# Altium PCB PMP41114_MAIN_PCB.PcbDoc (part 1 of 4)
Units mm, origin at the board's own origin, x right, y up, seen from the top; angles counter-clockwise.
Board outline 159.1 x 70 mm, 6 copper layers (Top Layer, Signal Layer 1, Signal Layer 2, Signal Layer 3, Signal Layer 4, Bottom Layer), stack 1.671 mm thick; 188 components, 146 nets, 720 pads, 326 vias.
Unrouted connection lines stored in the file: 209.
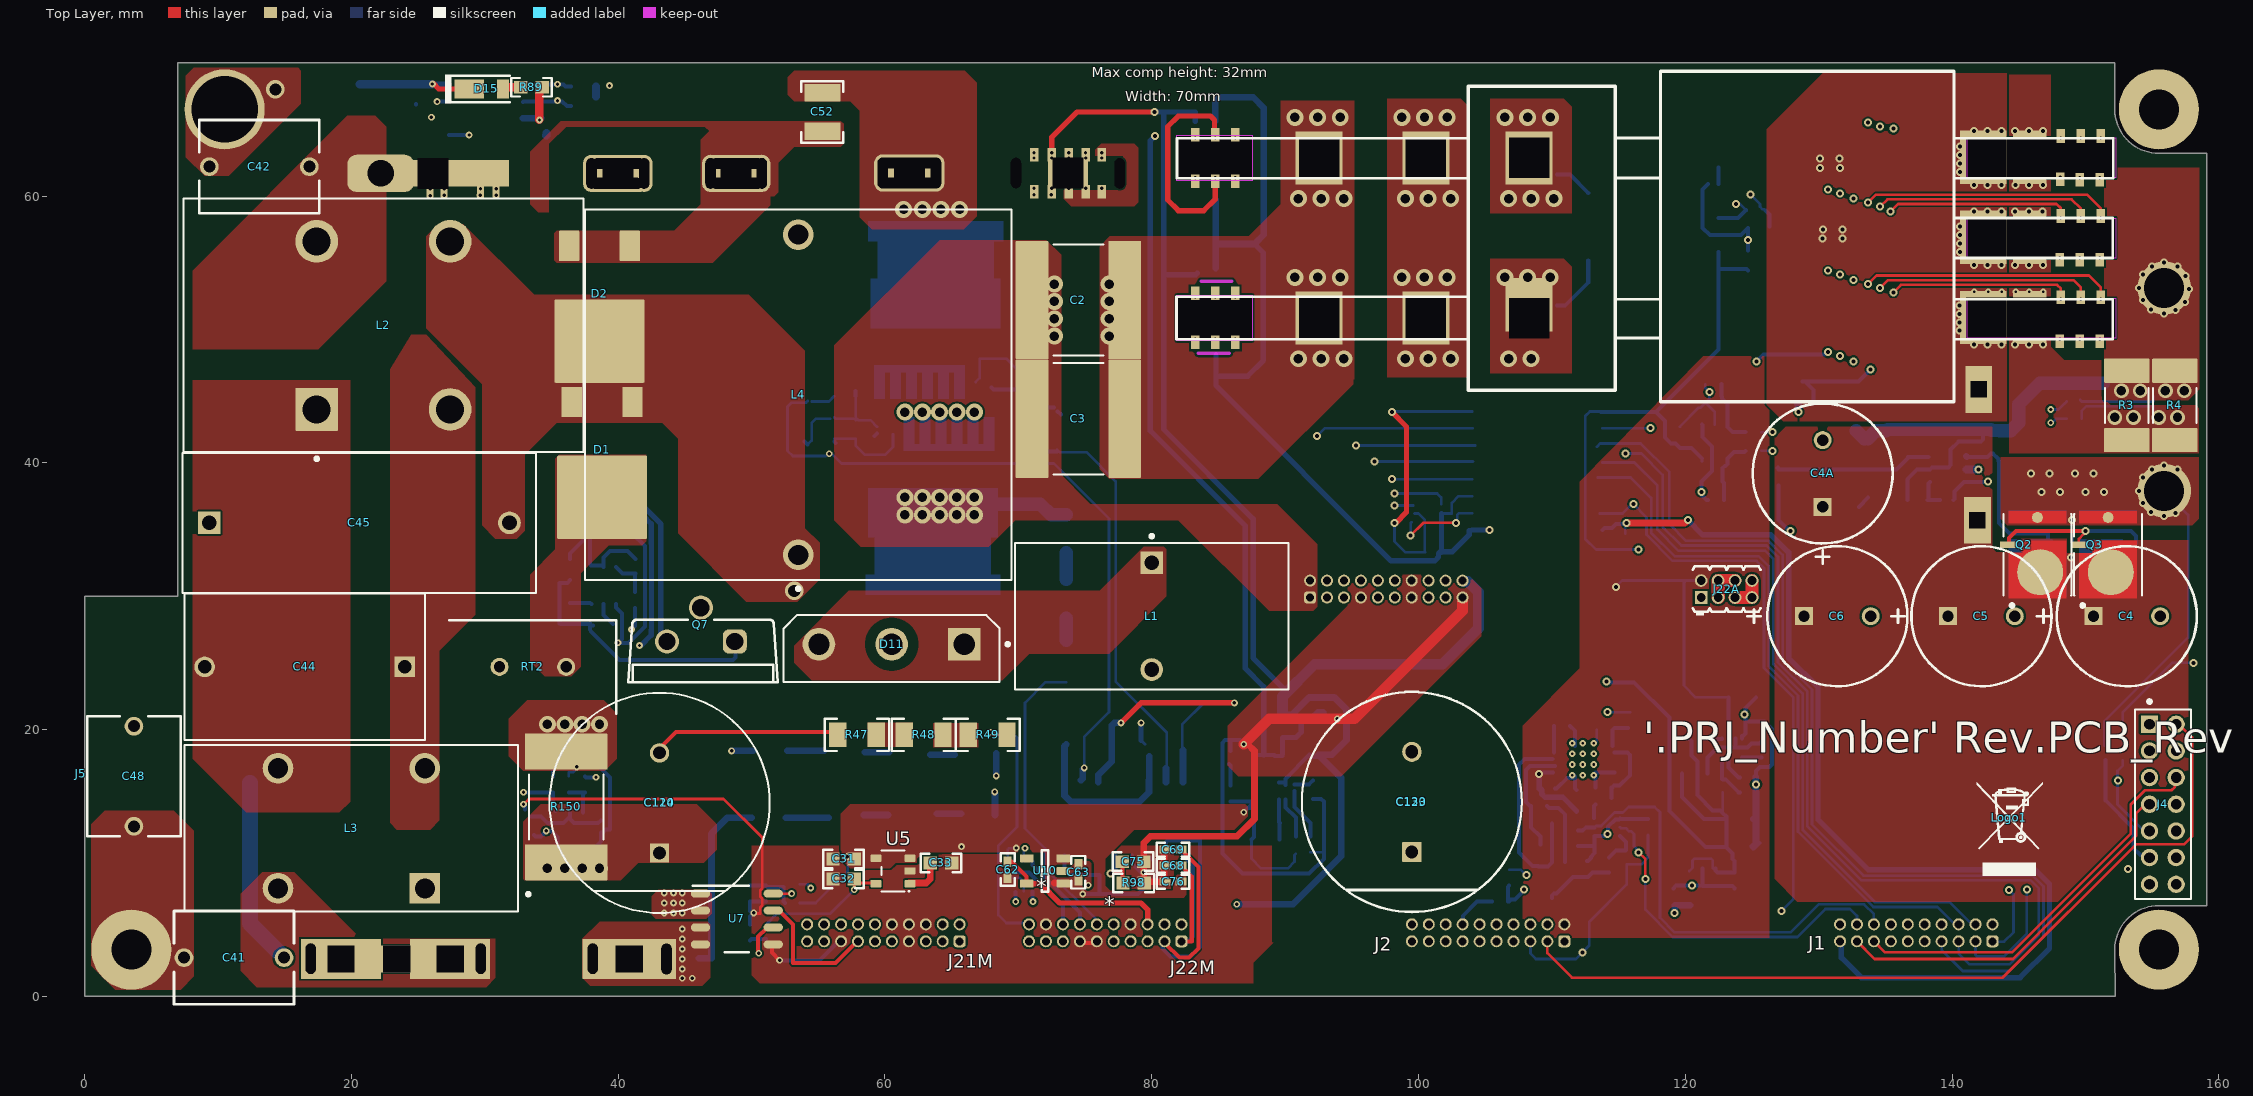
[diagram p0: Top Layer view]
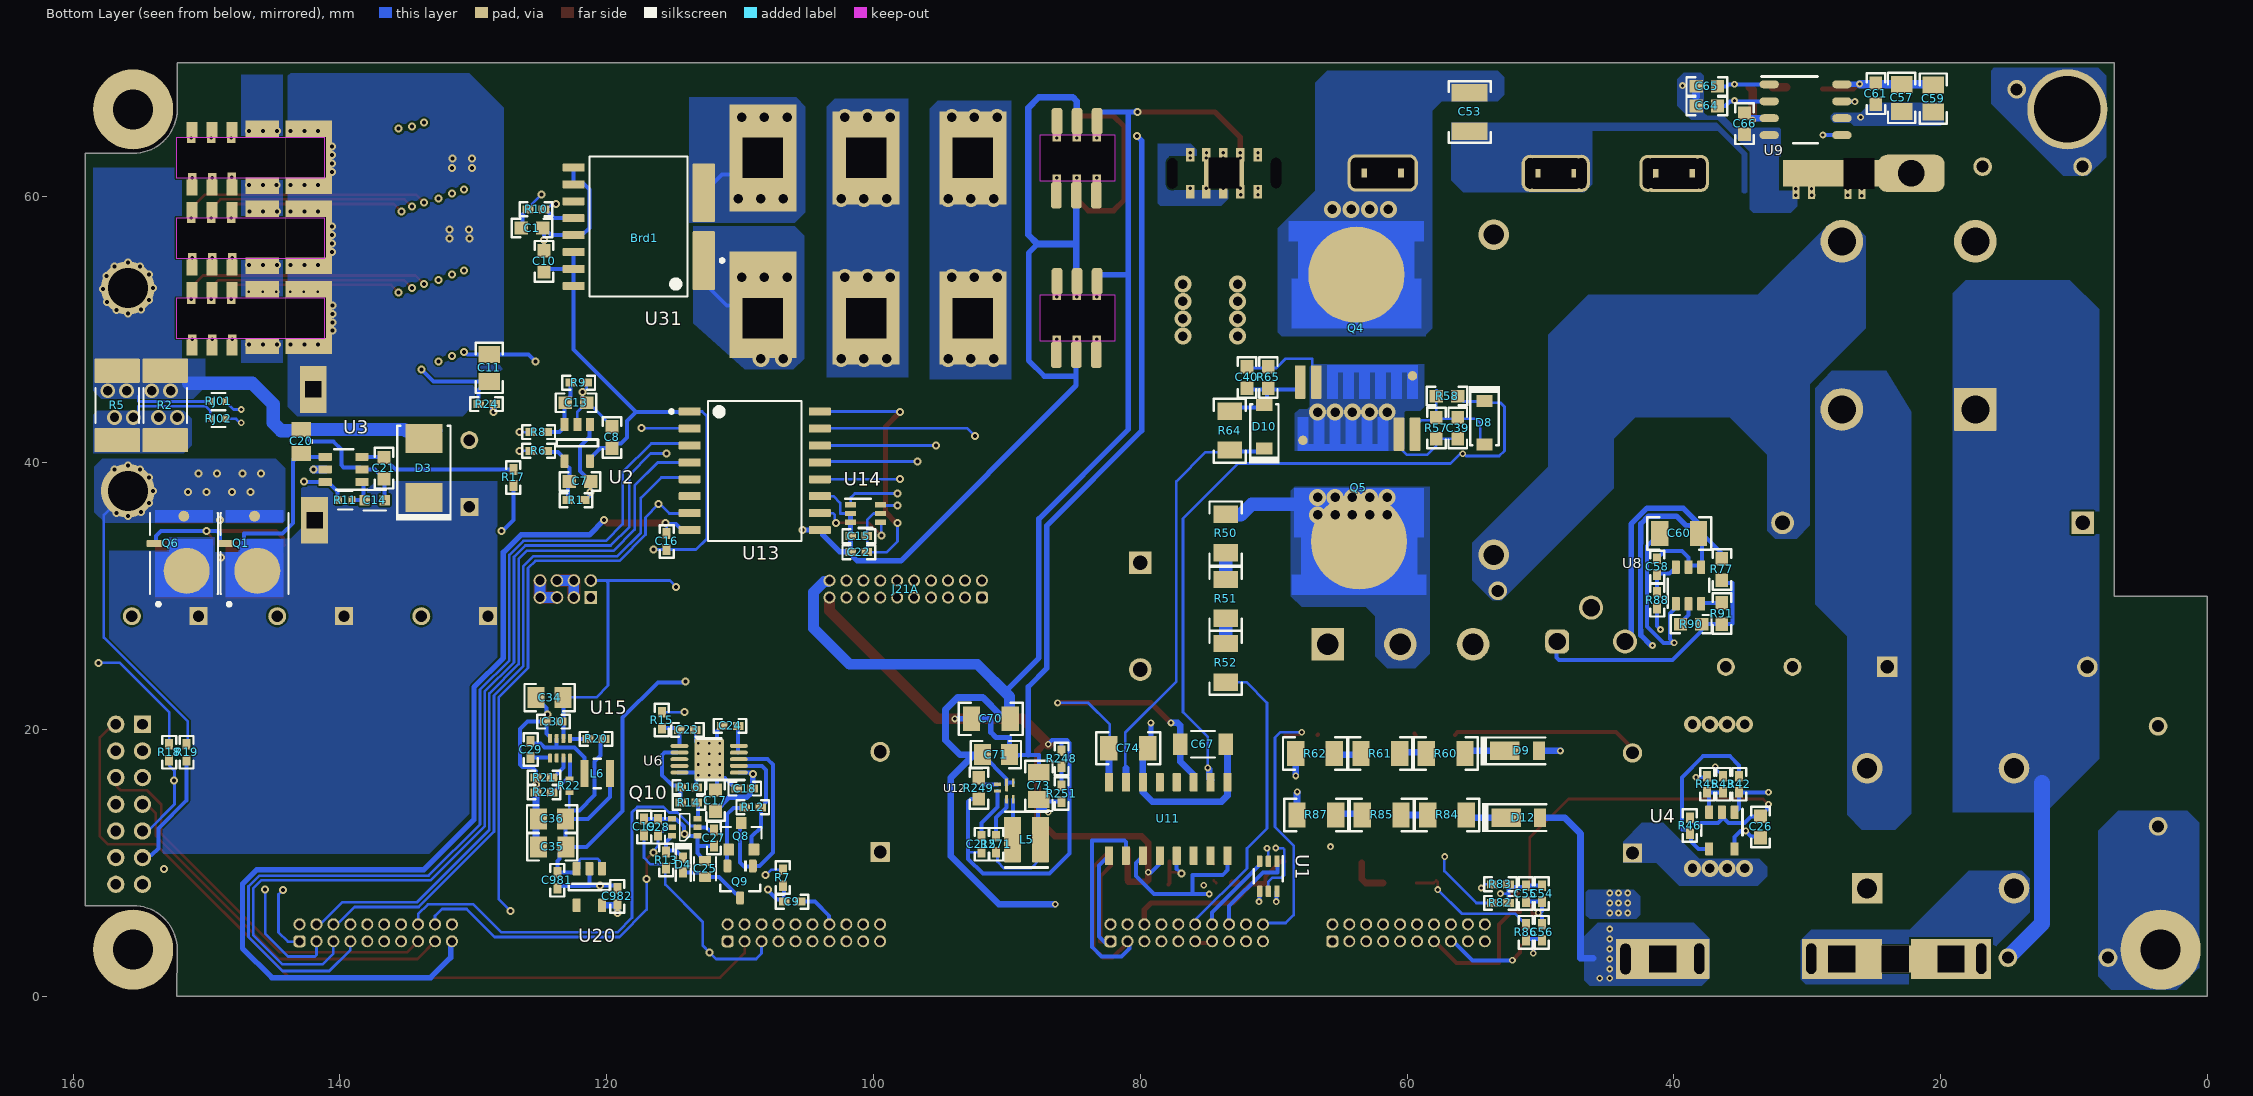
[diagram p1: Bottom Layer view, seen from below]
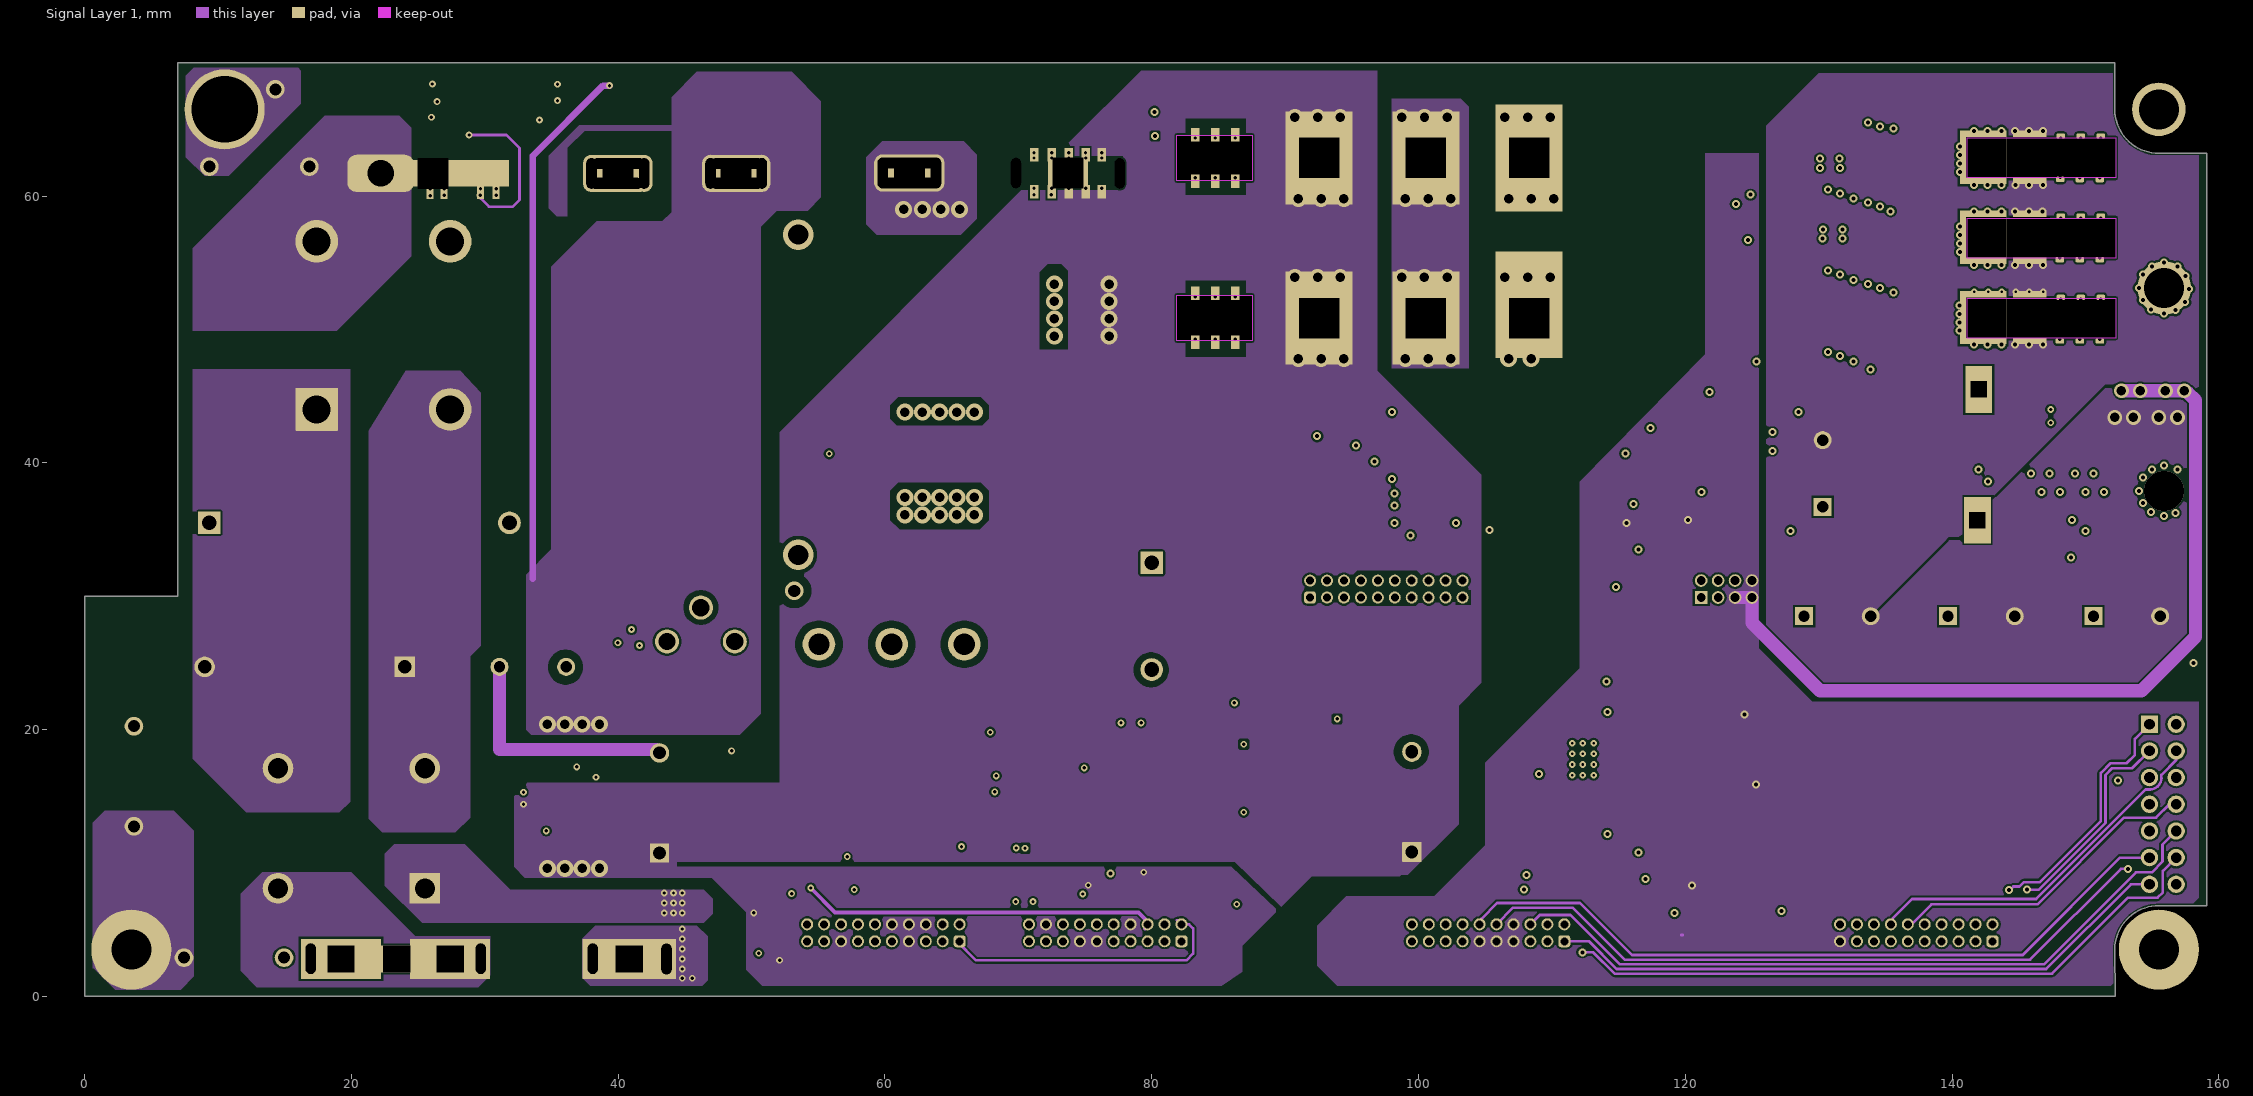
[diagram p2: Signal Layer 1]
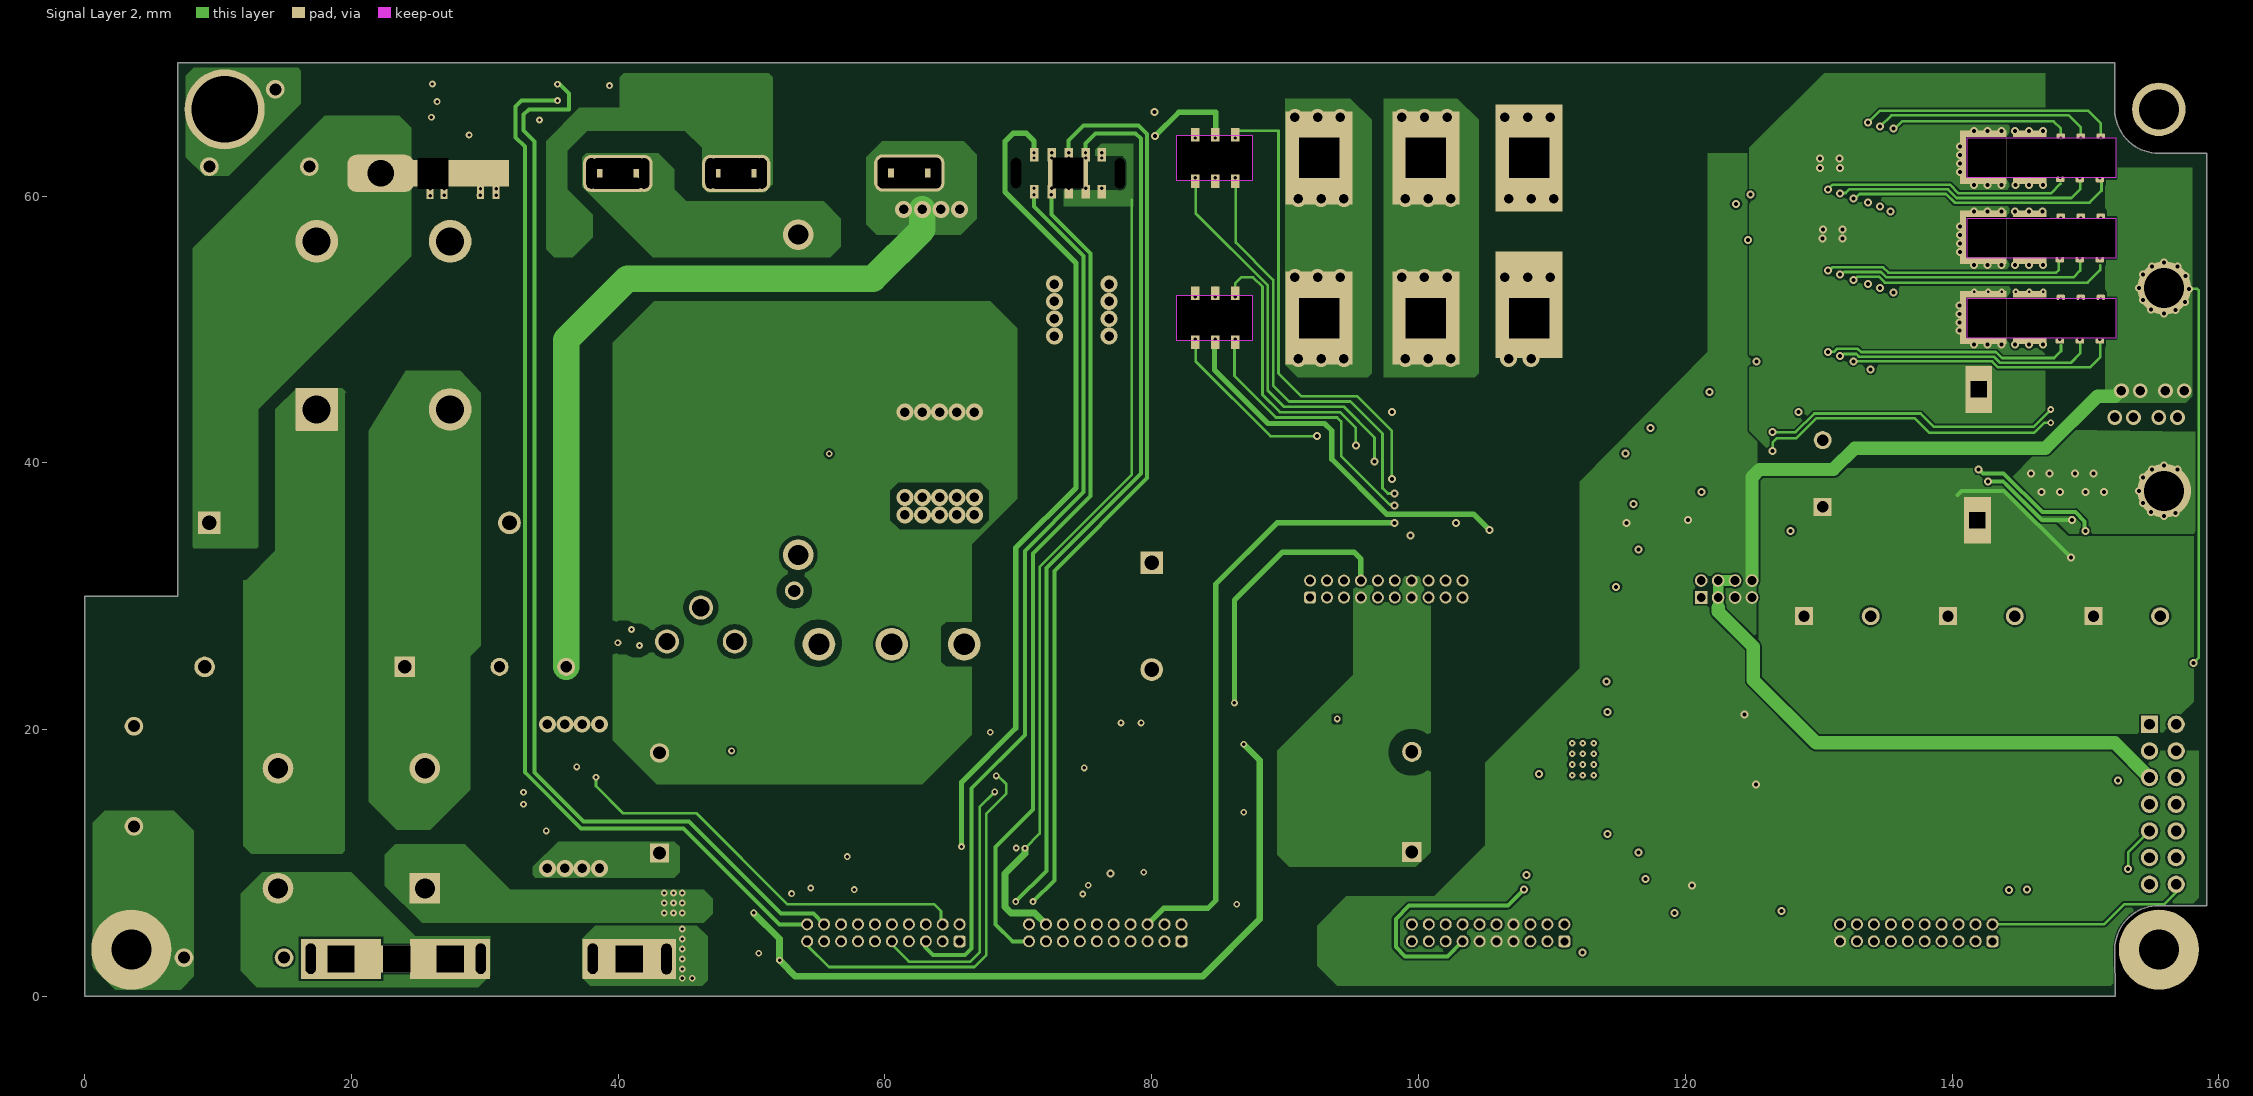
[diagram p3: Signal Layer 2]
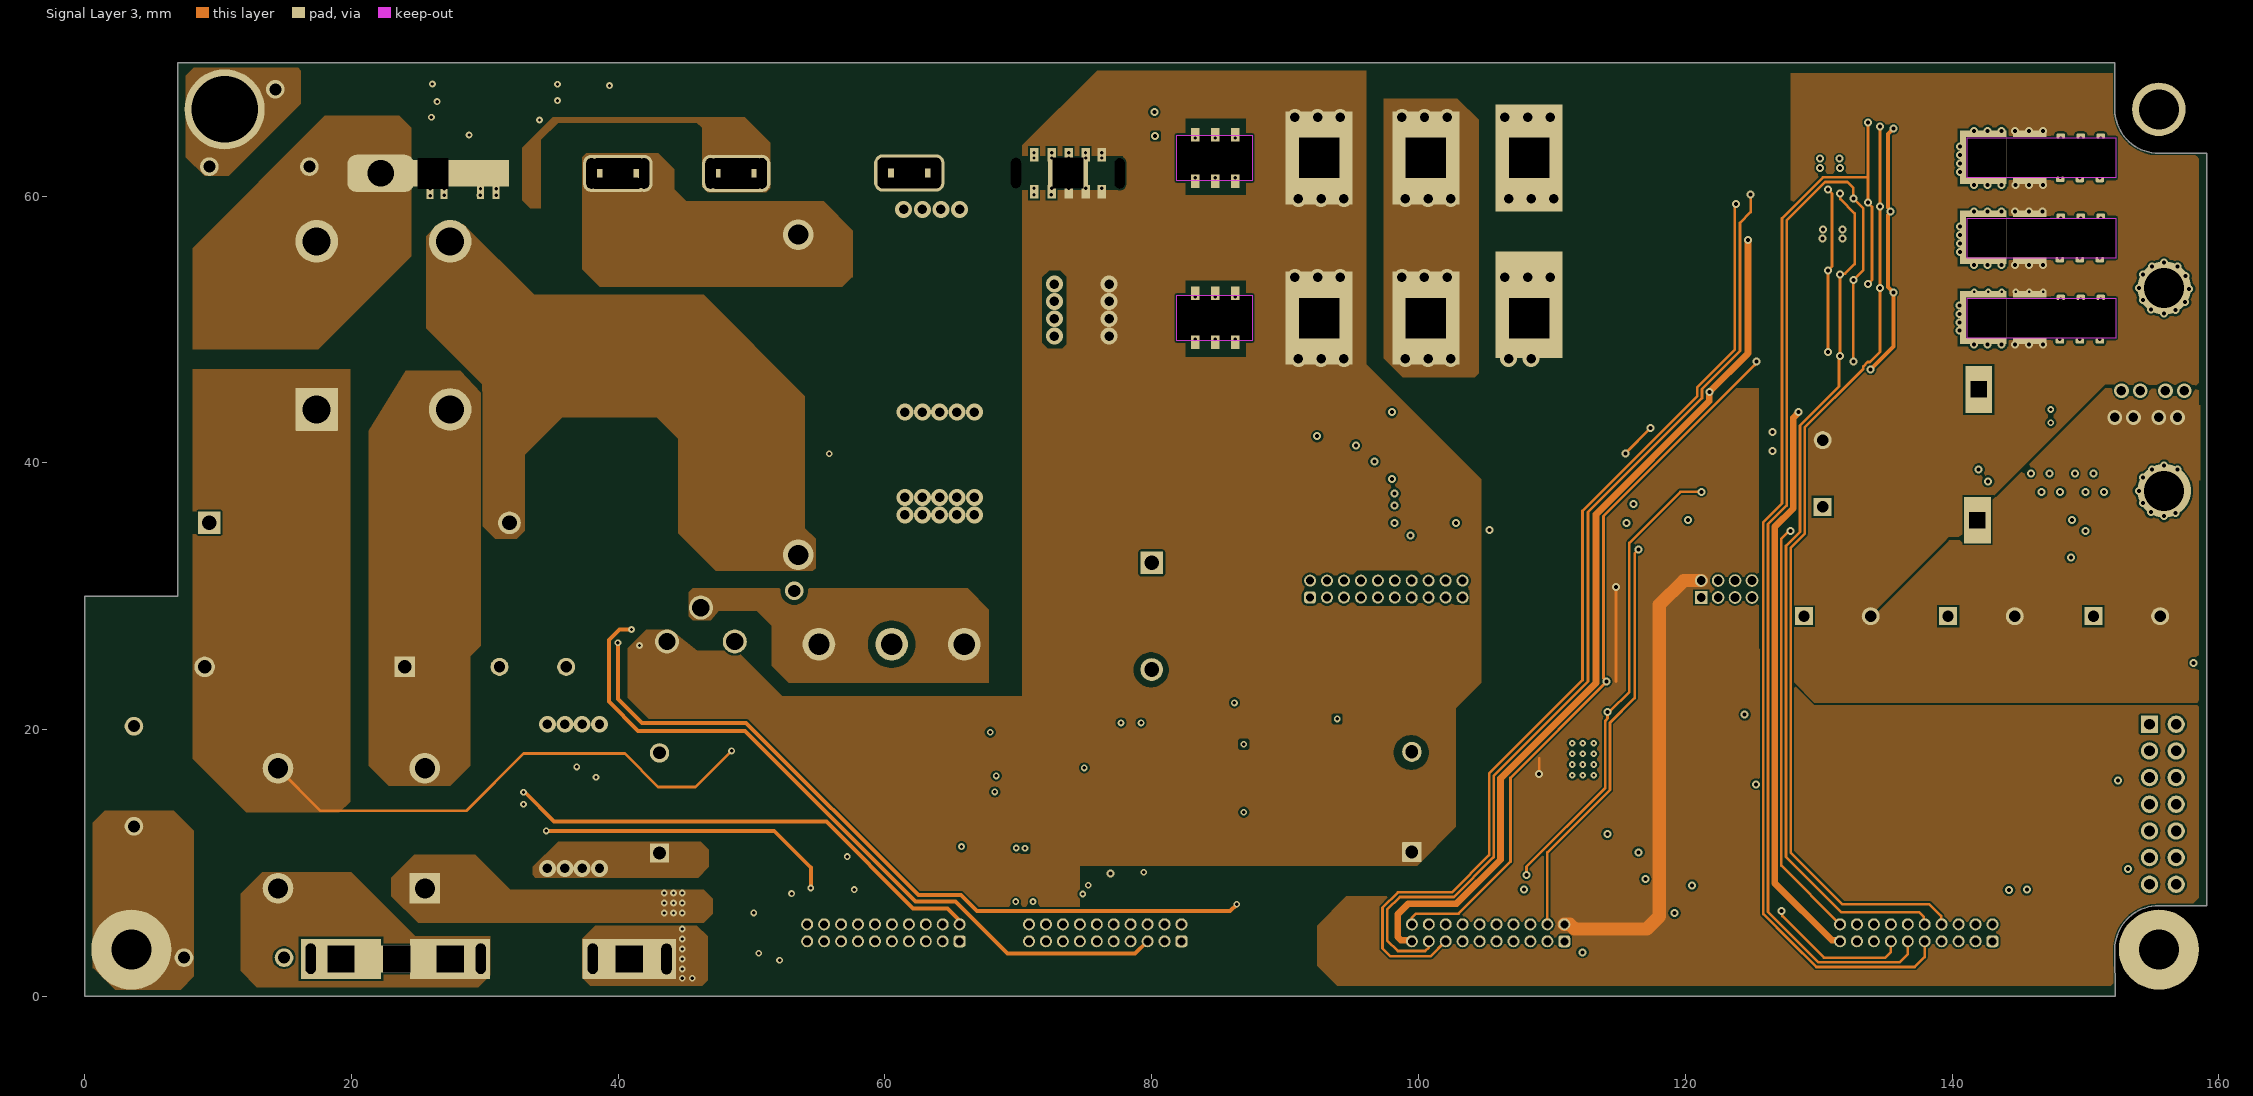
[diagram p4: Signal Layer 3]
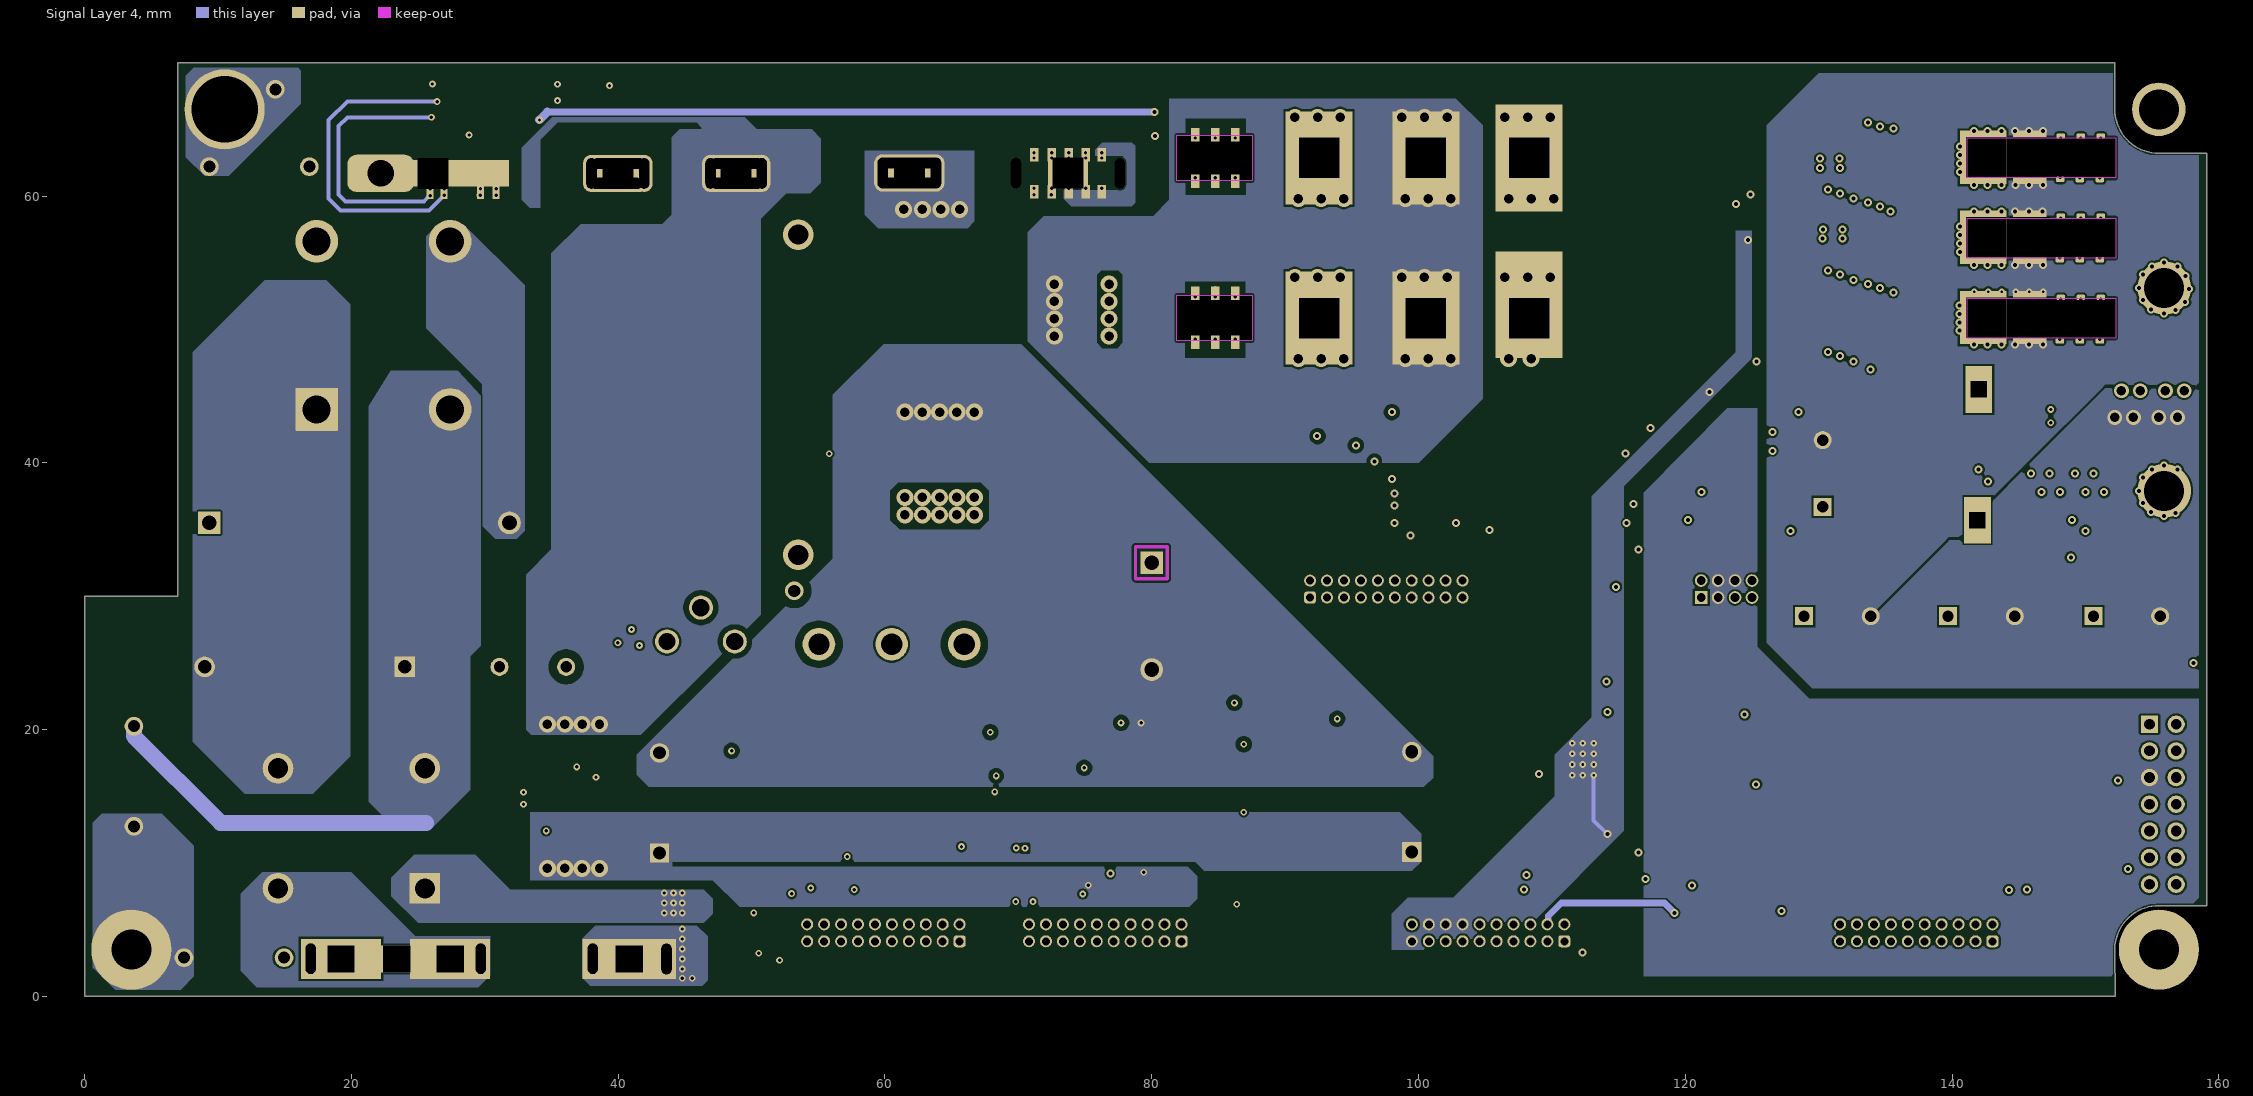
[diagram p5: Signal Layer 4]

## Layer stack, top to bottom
Top Solder: solder mask 0.0102, Solder Resist, Dk 3.5
Top Layer: signal copper 0.0711
Dielectric 2: prepreg 0.1778, Dk 4.2
Signal Layer 1: signal copper 0.0711
Dielectric 3: core 0.3556, Dk 4.2
Signal Layer 2: signal copper 0.0711
Dielectric1: prepreg 0.1778, FR-4, Dk 4.2
Signal Layer 3: signal copper 0.0711
Dielectric 4: core 0.3556, Dk 4.2
Signal Layer 4: signal copper 0.0711
Dielectric 5: prepreg 0.1778, Dk 4.2
Bottom Layer: signal copper 0.0711
Bottom Solder: solder mask 0.0102, Solder Resist, Dk 3.5

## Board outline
0,0 0,30 7,30 7,70 152.2,70 152.2,66.5 ccw(c155.5,66.5) 155.5,63.2 159.1,63.2 159.1,6.8 155.5,6.8 ccw(c155.5,3.5) 152.2,3.5 152.24,0

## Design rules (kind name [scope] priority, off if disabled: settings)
AcuteAngle [All] p1: minimum=4.50000000000000E+0001 checktracksonly=FALSE
AssemblyTestPointUsage [All] p1: valid=2
BoardOutlineClearance [All] p1: gap=0.15 ignorepadtopadclearanceinfootprint=FALSE
Clearance Clearance_3 [All] p1: gap=0.15 ignorepadtopadclearanceinfootprint=FALSE
Clearance Clearance_2 [InNetClass('HV') vs InNetClass('HV')] p2: gap=1 ignorepadtopadclearanceinfootprint=TRUE
Clearance Clearance_1 [InNetClass('MV') vs Not InNetClass('MV')] p3: gap=0.2 ignorepadtopadclearanceinfootprint=TRUE
Clearance Clearance_Keepouts [((IsTrack Or IsArc) And Not InPoly) And IsFree and IsKeepOut vs ((IsTrack Or IsArc) And Not InPoly) And IsFree and IsKeepOut] p4: gap=0.3 ignorepadtopadclearanceinfootprint=FALSE
Clearance Clearance_BoardEdge_MountingHoles [OnCopper and InComponentClass('Mounting Holes') vs IsKeepOut] p5: gap=0.3 ignorepadtopadclearanceinfootprint=FALSE
Clearance Clearance_BoardEdge_Poly [OnCopper and InPoly vs IsKeepOut] p6: gap=0.635 ignorepadtopadclearanceinfootprint=FALSE except(0: Arc-Hole Track-Hole SMDPad-Hole THPad-Hole Via-Hole Fill-Hole Poly-Hole Region-Hole Text-Hole)
Clearance Clearance_BoardEdge [OnCopper and Not InComponentClass('Logo') and not InComponentClass('FiducialMark') and not InRegion(1000,500,4000,800) and Not IsKeepout vs IsKeepOut] p7: gap=1.905 ignorepadtopadclearanceinfootprint=FALSE except(0: Arc-Hole Track-Hole SMDPad-Hole THPad-Hole Via-Hole Fill-Hole Poly-Hole Region-Hole Text-Hole)
Clearance Clearance_Poly [InPolygon] p8: gap=0 ignorepadtopadclearanceinfootprint=FALSE
Clearance [All] p9: gap=0.2 ignorepadtopadclearanceinfootprint=FALSE except(0: Arc-SMDPad Arc-Hole Track-Hole SMDPad-Hole THPad-Hole Via-Hole Fill-Hole Poly-Hole Region-Hole Text-Hole; 0.127: Arc-Arc Arc-Track Arc-THPad Arc-Via Arc-Fill Track-Track Track-SMDPad Track-THPad Track-Via Track-Fill SMDPad-SMDPad SMDPad-THPad SMDPad-Via SMDPad-Fill THPad-THPad THPad-Via THPad-Fill Via-Via Via-Fill Fill-Fill)
ComponentClearance ComponentClearance_MountingHoles_FiducialMarks [InComponentClass('Mounting Holes') vs InComponentClass('FiducialMark')] p1: gap=0.508 collisioncheckmode=3 verticalgap=0.178 showdistances=FALSE
ComponentClearance ComponentClearance_Shunt [InComponentClass('Header') vs InComponentClass('Shunt')] p2: gap=0 collisioncheckmode=3 verticalgap=0 showdistances=FALSE
ComponentClearance ComponentClearance_Logo [InComponentClass('Logo')] p3: gap=0.127 collisioncheckmode=3 verticalgap=0.254 showdistances=FALSE
ComponentClearance ComponentClearance_ScrewToNut [(HasFootprint('KEYSTONE_4824')) vs (HasFootprint('Keystone_1903C'))] p4: gap=0 collisioncheckmode=3 verticalgap=0 showdistances=FALSE
ComponentClearance ComponentClearance_MountingHoles [InComponentClass('Mounting Holes')] p5: gap=0.508 collisioncheckmode=3 verticalgap=0.178 showdistances=FALSE
ComponentClearance ComponentClearance_SmallPassives [HasFootprint('0201*') or HasFootprint('0402*') or HasFootprint('0508') or HasFootprint('0603*') or HasFootprint('0612') or HasFootprint('0805*') or HasFootprint('0815*') or HasFootprint('0830*') or HasFootprint('1206*') or HasFootprint('1210*') or HasFootprint('1808*') or HasFootprint('1812*') or HasFootprint('1825*') or HasFootprint('2010*') or HasFootprint('2220*') or HasFootprint('2225*') or HasFootprint('2512*') or HasFootprint('2728*') or HasFootprint('3518*') vs HasFootprint('0201*') or HasFootprint('0402*') or HasFootprint('0508') or HasFootprint('0603*') or HasFootprint('0612') or HasFootprint('0805*') or HasFootprint('0815*') or HasFootprint('0830*') or HasFootprint('1206*') or HasFootprint('1210*') or HasFootprint('1808*') or HasFootprint('1812*') or HasFootprint('1825*') or HasFootprint('2010*') or HasFootprint('2220*') or HasFootprint('2225*') or HasFootprint('2512*') or HasFootprint('2728*') or HasFootprint('3518*')] p6: gap=0.127 collisioncheckmode=3 verticalgap=0.025 showdistances=FALSE
ComponentClearance ComponentClearance_THtoSMT [IsThruComponent vs IsSMTComponent] p7: gap=0.254 collisioncheckmode=3 verticalgap=0.178 showdistances=FALSE
ComponentClearance ComponentClearance_THtoTH [IsThruComponent vs IsThruComponent] p8: gap=0.254 collisioncheckmode=3 verticalgap=0.178 showdistances=FALSE
ComponentClearance [All] p9: gap=0.254 collisioncheckmode=3 verticalgap=0.178 showdistances=FALSE
DiffPairsRouting [All] p1: maxlimit=2.54 minlimit=0.254 mostfreqgap=0.254 toplayer_minwidth=0.381 toplayer_maxwidth=0.381 toplayer_prefwidth=0.381 midlayer1_minwidth=0.381 midlayer1_maxwidth=0.381 midlayer1_prefwidth=0.381 midlayer2_minwidth=0.381 midlayer2_maxwidth=0.381 midlayer2_prefwidth=0.381 midlayer3_minwidth=0.381 midlayer3_maxwidth=0.381 midlayer3_prefwidth=0.381 midlayer4_minwidth=0.381 midlayer4_maxwidth=0.381 midlayer4_prefwidth=0.381 bottomlayer_minwidth=0.381 bottomlayer_maxwidth=0.381 bottomlayer_prefwidth=0.381 maxuncoupledlength=25.4
FabricationTestPointUsage TestPointUsage [All] p1: valid=2 allowmultiple=FALSE
FabricationTestpoint Testpoint [All] p1: side=3 testpointundercomponent=TRUE minsize=1.016 maxsize=2.54 preferedsize=1.524 minholesize=0 maxholesize=1.016 preferedholesize=0.813 testpointgrid=0.025 allowsidetop=TRUE allowsidebottom=TRUE usegrid=TRUE gridtolerance=0
FanoutControl Fanout_LCC [IsLCC] p1: bgadir=Out bgaviamode=Centered fanoutstyle=Auto fanoutdirection=Alternating viagrid=0.025 // Fanout_LCC (Default Rule)
FanoutControl Fanout_BGA [IsBGA] p2: bgadir=Out bgaviamode=Centered fanoutstyle=Auto fanoutdirection=Alternating viagrid=0.025 // Fanout_BGA (Default Rule)
Height [All] p1: minheight=0 maxheight=76.2 prefheight=12.7
HoleSize [All] p1: absolutevalues=TRUE maxlimit=12.725 minlimit=0.178 maxpercent=80.000 minpercent=20.000
MinimumAnnularRing MinimumAnnularRing_ThermalPadVias [IsVia and InAnyComponent] p1: minimumring=0.15
MinimumAnnularRing [All] p2: minimumring=0.127
MinimumSolderMaskSliver MinimumSolderMaskSliver_Logo [InComponentClass('Logo') vs InComponentClass('Logo')] p1: minsoldermaskwidth=0.018
MinimumSolderMaskSliver [All] p2: minsoldermaskwidth=0.018
PlaneClearance [All] p1: clearance=0.5
PlaneConnect [All] p1: planeconnectstyle=Direct reliefexpansion=0.254 reliefentries=4 reliefconductorwidth=0.254 reliefairgap=0.254
PolygonConnect PolygonConnect_16 [All vs IsNamedPolygon('C106_2') Or IsNamedPolygon('Vout') Or IsNamedPolygon('IN+') Or IsNamedPolygon('Q203_5') Or IsNamedPolygon('IN+') Or IsNamedPolygon('Q201_5') Or IsNamedPolygon('C108_2') Or IsNamedPolygon('SGND') Or IsNamedPolygon('IN+') Or IsNamedPolygon('SGND') Or IsNamedPolygon('Q203_5') Or IsNamedPolygon('IN+') Or IsNamedPolygon('SGND') Or IsNamedPolygon('GND') Or IsNamedPolygon('C113_2') Or IsNamedPolygon('C107_2') Or IsNamedPolygon('C107_2') Or IsNamedPolygon('Vout') Or IsNamedPolygon('SIGNAL_LAYER_1_GND_P074') Or IsNamedPolygon('HV') Or IsNamedPolygon('C108_2') Or IsNamedPolygon('C103_2') Or IsNamedPolygon('Q201_5') Or IsNamedPolygon('Vout') Or IsNamedPolygon('C109_2') Or IsNamedPolygon('Q201_5') Or IsNamedPolygon('GND') Or IsNamedPolygon('C107_2') Or IsNamedPolygon('C102_1') Or IsNamedPolygon('GND') Or IsNamedPolygon('SGND') Or IsNamedPolygon('HS') Or IsNamedPolygon('Q203_5') Or IsNamedPolygon('Q201_5') Or IsNamedPolygon('Q203_5')] p1: connectstyle=Direct reliefconductorwidth=0.254 reliefentries=4 polygonreliefangle="90 Angle" airgapwidth=0.254
PolygonConnect PolygonConnect_15 [All vs IsNamedPolygon('C109_2') Or IsNamedPolygon('C107_2') Or IsNamedPolygon('HV') Or IsNamedPolygon('Q203_5') Or IsNamedPolygon('C107_2') Or IsNamedPolygon('HS') Or IsNamedPolygon('Q201_5') Or IsNamedPolygon('Q203_5') Or IsNamedPolygon('C106_2') Or IsNamedPolygon('C108_2') Or IsNamedPolygon('Vout') Or IsNamedPolygon('Q203_5') Or IsNamedPolygon('C108_2') Or IsNamedPolygon('C113_2') Or IsNamedPolygon('Q203_5') Or IsNamedPolygon('Q201_5') Or IsNamedPolygon('C107_2') Or IsNamedPolygon('C102_1') Or IsNamedPolygon('SGND') Or IsNamedPolygon('GND') Or IsNamedPolygon('SGND') Or IsNamedPolygon('GND') Or IsNamedPolygon('IN+') Or IsNamedPolygon('IN+') Or IsNamedPolygon('Q201_5') Or IsNamedPolygon('Q201_5') Or IsNamedPolygon('SGND') Or IsNamedPolygon('SGND') Or IsNamedPolygon('Vout') Or IsNamedPolygon('Vout') Or IsNamedPolygon('IN+') Or IsNamedPolygon('GND') Or IsNamedPolygon('IN+') Or IsNamedPolygon('GND')] p2: connectstyle=Direct reliefconductorwidth=0.254 reliefentries=4 polygonreliefangle="90 Angle" airgapwidth=0.254
PolygonConnect PolygonConnect_14 [All vs IsNamedPolygon('C106_2') Or IsNamedPolygon('C107_2') Or IsNamedPolygon('C107_2') Or IsNamedPolygon('C107_2') Or IsNamedPolygon('C102_1') Or IsNamedPolygon('Q203_5') Or IsNamedPolygon('Vout') Or IsNamedPolygon('Q203_5') Or IsNamedPolygon('Q203_5') Or IsNamedPolygon('Q201_5') Or IsNamedPolygon('C108_2') Or IsNamedPolygon('Q203_5') Or IsNamedPolygon('HS') Or IsNamedPolygon('HV') Or IsNamedPolygon('C108_2') Or IsNamedPolygon('Q201_5') Or IsNamedPolygon('C109_2') Or IsNamedPolygon('Q201_5') Or IsNamedPolygon('Q201_5') Or IsNamedPolygon('C113_2')] p3: connectstyle=Direct reliefconductorwidth=0.254 reliefentries=4 polygonreliefangle="90 Angle" airgapwidth=0.254
PolygonConnect PolygonConnect_13 [All vs IsNamedPolygon('C102_1') Or IsNamedPolygon('HV') Or IsNamedPolygon('C107_2') Or IsNamedPolygon('C109_2') Or IsNamedPolygon('C107_2') Or IsNamedPolygon('C108_2') Or IsNamedPolygon('C106_2') Or IsNamedPolygon('C108_2') Or IsNamedPolygon('C113_2') Or IsNamedPolygon('C107_2')] p4: connectstyle=Direct reliefconductorwidth=0.254 reliefentries=4 polygonreliefangle="90 Angle" airgapwidth=0.254
PolygonConnect PolygonConnect_12 [All vs IsNamedPolygon('C107_2') Or IsNamedPolygon('C113_2') Or IsNamedPolygon('C106_2') Or IsNamedPolygon('C107_2') Or IsNamedPolygon('C107_2') Or IsNamedPolygon('C102_1')] p5: connectstyle=Direct reliefconductorwidth=0.254 reliefentries=4 polygonreliefangle="90 Angle" airgapwidth=0.254
PolygonConnect PolygonConnect_11 [All vs IsNamedPolygon('C106_2') Or IsNamedPolygon('C102_1') Or IsNamedPolygon('C107_2') Or IsNamedPolygon('C107_2') Or IsNamedPolygon('C107_2')] p6: connectstyle=Direct reliefconductorwidth=0.254 reliefentries=4 polygonreliefangle="90 Angle" airgapwidth=0.254
PolygonConnect PolygonConnect_10 [All vs IsNamedPolygon('C106_2')] p7: connectstyle=Direct reliefconductorwidth=0.254 reliefentries=4 polygonreliefangle="90 Angle" airgapwidth=0.254
PolygonConnect PolygonConnect_9 [All vs IsNamedPolygon('C11_1') Or IsNamedPolygon('Vin') Or IsNamedPolygon('Vin') Or IsNamedPolygon('5V') Or IsNamedPolygon('D6_2') Or IsNamedPolygon('Q3_3') Or IsNamedPolygon('GND2') Or IsNamedPolygon('GND2') Or IsNamedPolygon('GND') Or IsNamedPolygon('Q3_4') Or IsNamedPolygon('12V5') Or IsNamedPolygon('GND') Or IsNamedPolygon('12V5') Or IsNamedPolygon('D3_1')] p8: connectstyle=Direct reliefconductorwidth=0.254 reliefentries=4 polygonreliefangle="90 Angle" airgapwidth=0.254
PolygonConnect PolygonConnect_8 [All vs IsNamedPolygon('C11_1') Or IsNamedPolygon('Vin') Or IsNamedPolygon('12V5') Or IsNamedPolygon('Q3_3') Or IsNamedPolygon('GND2') Or IsNamedPolygon('GND2') Or IsNamedPolygon('5V') Or IsNamedPolygon('Q3_4') Or IsNamedPolygon('12V5')] p9: connectstyle=Direct reliefconductorwidth=0.254 reliefentries=4 polygonreliefangle="90 Angle" airgapwidth=0.254
PolygonConnect PolygonConnect_7 [All vs IsNamedPolygon('GND2') Or IsNamedPolygon('GND2') Or IsNamedPolygon('5V') Or IsNamedPolygon('12V5') Or IsNamedPolygon('12V5') Or IsNamedPolygon('C11_1')] p10: connectstyle=Direct reliefconductorwidth=0.254 reliefentries=4 polygonreliefangle="90 Angle" airgapwidth=0.254
PolygonConnect PolygonConnect_6 [All vs IsNamedPolygon('GND2') Or IsNamedPolygon('SGND') Or IsNamedPolygon('GND1') Or IsNamedPolygon('C901_1') Or IsNamedPolygon('SGND') Or IsNamedPolygon('GND2') Or IsNamedPolygon('GND1')] p11: connectstyle=Direct reliefconductorwidth=0.254 reliefentries=4 polygonreliefangle="90 Angle" airgapwidth=0.254
PolygonConnect PolygonConnect_5 [All vs IsNamedPolygon('GND1') Or IsNamedPolygon('GND1')] p12: connectstyle=Direct reliefconductorwidth=0.254 reliefentries=4 polygonreliefangle="90 Angle" airgapwidth=0.254
PolygonConnect PolygonConnect_4 [All vs IsNamedPolygon('C21_1') Or IsNamedPolygon('C5_1') Or IsNamedPolygon('C12_2') Or IsNamedPolygon('C2_2') Or IsNamedPolygon('C13_1') Or IsNamedPolygon('C28_1') Or IsNamedPolygon('C6_1') Or IsNamedPolygon('GND') Or IsNamedPolygon('GND2') Or IsNamedPolygon('C14_1') Or IsNamedPolygon('C13_1') Or IsNamedPolygon('Q1_3') Or IsNamedPolygon('C14_1') Or IsNamedPolygon('C5_1') Or IsNamedPolygon('GND2') Or IsNamedPolygon('C28_1') Or IsNamedPolygon('D5_2') Or IsNamedPolygon('D6_2') Or IsNamedPolygon('D2_1') Or IsNamedPolygon('C12_2') Or IsNamedPolygon('D2_1') Or IsNamedPolygon('C4_1') Or IsNamedPolygon('C4_1') Or IsNamedPolygon('C2_2') Or IsNamedPolygon('GND') Or IsNamedPolygon('C33_1') Or IsNamedPolygon('C9_1')] p13: connectstyle=Direct reliefconductorwidth=0.254 reliefentries=4 polygonreliefangle="90 Angle" airgapwidth=0.254
PolygonConnect PolygonConnect_3 [All vs IsNamedPolygon('C28_1') Or IsNamedPolygon('C12_2') Or IsNamedPolygon('C28_1') Or IsNamedPolygon('C9_1') Or IsNamedPolygon('D5_2') Or IsNamedPolygon('C12_2') Or IsNamedPolygon('C2_2') Or IsNamedPolygon('C14_1') Or IsNamedPolygon('C4_1') Or IsNamedPolygon('C14_1') Or IsNamedPolygon('D6_2') Or IsNamedPolygon('GND2') Or IsNamedPolygon('Q1_3') Or IsNamedPolygon('C5_1') Or IsNamedPolygon('D2_1') Or IsNamedPolygon('C4_1') Or IsNamedPolygon('C13_1') Or IsNamedPolygon('C5_1') Or IsNamedPolygon('C13_1') Or IsNamedPolygon('C33_1') Or IsNamedPolygon('D2_1') Or IsNamedPolygon('GND') Or IsNamedPolygon('GND') Or IsNamedPolygon('GND2') Or IsNamedPolygon('C2_2') Or IsNamedPolygon('C6_1') Or IsNamedPolygon('C21_1')] p14: connectstyle=Direct reliefconductorwidth=0.254 reliefentries=4 polygonreliefangle="90 Angle" airgapwidth=0.254
PolygonConnect PolygonConnect_2 [All vs IsNamedPolygon('C21_1') Or IsNamedPolygon('C4_1') Or IsNamedPolygon('D5_2') Or IsNamedPolygon('C5_1') Or IsNamedPolygon('C14_1') Or IsNamedPolygon('C13_1') Or IsNamedPolygon('C4_1') Or IsNamedPolygon('C33_1') Or IsNamedPolygon('C12_2') Or IsNamedPolygon('D2_1') Or IsNamedPolygon('C2_2') Or IsNamedPolygon('C28_1') Or IsNamedPolygon('C12_2') Or IsNamedPolygon('D2_1') Or IsNamedPolygon('C5_1') Or IsNamedPolygon('Q1_3') Or IsNamedPolygon('GND') Or IsNamedPolygon('D6_2') Or IsNamedPolygon('C6_1') Or IsNamedPolygon('C2_2') Or IsNamedPolygon('C14_1') Or IsNamedPolygon('C28_1') Or IsNamedPolygon('C13_1') Or IsNamedPolygon('C9_1') Or IsNamedPolygon('GND')] p15: connectstyle=Direct reliefconductorwidth=0.254 reliefentries=4 polygonreliefangle="90 Angle" airgapwidth=0.254
PolygonConnect PolygonConnect_1 [All vs IsNamedPolygon('C28_1') Or IsNamedPolygon('D5_2') Or IsNamedPolygon('C5_1') Or IsNamedPolygon('C5_1') Or IsNamedPolygon('D2_1') Or IsNamedPolygon('C21_1') Or IsNamedPolygon('C9_1') Or IsNamedPolygon('C4_1') Or IsNamedPolygon('C14_1') Or IsNamedPolygon('C28_1') Or IsNamedPolygon('C6_1') Or IsNamedPolygon('C12_2') Or IsNamedPolygon('C33_1') Or IsNamedPolygon('C4_1') Or IsNamedPolygon('C13_1') Or IsNamedPolygon('C12_2') Or IsNamedPolygon('D6_2') Or IsNamedPolygon('C2_2') Or IsNamedPolygon('C14_1') Or IsNamedPolygon('D2_1') Or IsNamedPolygon('C2_2') Or IsNamedPolygon('C13_1')] p16: connectstyle=Direct reliefconductorwidth=0.254 reliefentries=4 polygonreliefangle="90 Angle" airgapwidth=0.254
PolygonConnect [All] p17: connectstyle=Direct reliefconductorwidth=0.254 reliefentries=4 polygonreliefangle="90 Angle" airgapwidth=0.254
RoutingVias ThermalPadVias [IsVia and not InNet('SGND')and not InNet('Vout')] p1: holewidth=0.2 width=0.5 viastyle="Through Hole" minholewidth=0.2 minwidth=0.5 maxholewidth=1 maxwidth=2
RoutingVias [IsVia and not InNet('SGND')and not InNet('Vout')] p2: holewidth=0.406 width=0.864 viastyle="Through Hole" minholewidth=0.2 minwidth=0.508 maxholewidth=1.016 maxwidth=1.651
SilkToSilkClearance SilkToSilkClearance_Pb-FreeLogo [(HasFootprint('Pb-Free_Overlay_Medium') OR HasFootprint('Pb-Free_Overlay_Small')) vs (HasFootprint('Pb-Free_Overlay_Medium') OR HasFootprint('Pb-Free_Overlay_Small'))] p1: silktosilkclearance=0
SilkToSilkClearance [All] p2: silktosilkclearance=0
SilkToSolderMaskClearance "Silk to Solder Mask Opening" [All] p1: minsilkscreentomaskgap=0 clearancetoexposedcopper=FALSE
SolderMaskExpansion [All] p1: expansion=0.05 istentingtop=FALSE
SupplyNets "Schematic Supply Nets_7" [InNet('AGND')] p1: voltage=0.000
SupplyNets "Schematic Supply Nets_5" [InNet('12Vp_h')] p2: voltage=0.000
SupplyNets "Schematic Supply Nets_8" [InNet('SGND')] p3: voltage=0.000
SupplyNets "Schematic Supply Nets_12" [InNet('12VS')] p4: voltage=0.000
SupplyNets "Schematic Supply Nets_11" [InNet('5Vp')] p5: voltage=0.000
SupplyNets "Schematic Supply Nets_2" [InNet('PE')] p6: voltage=0.000
SupplyNets "Schematic Supply Nets" [InNet('5Vc-s')] p7: voltage=0.000
SupplyNets "Schematic Supply Nets_10" [InNet('3V3')] p8: voltage=0.000
SupplyNets "Schematic Supply Nets_9" [InNet('3.3Vc-s')] p9: voltage=0.000
SupplyNets "Schematic Supply Nets_6" [InNet('12Vp')] p10: voltage=0.000
SupplyNets "Schematic Supply Nets_4" [InNet('54Vout')] p11: voltage=0.000
SupplyNets "Schematic Supply Nets_3" [InNet('12VSB')] p12: voltage=0.000
SupplyNets "Schematic Supply Nets_1" [InNet('PGND')] p13: voltage=0.000
UnpouredPolygon [All] p1: allowunpoured=TRUE allowshelved=TRUE
Width [All] p1: maxlimit=2.54 minlimit=0.152 preferedwidth=0.2 checkconnectedcopper=TRUE
15 further rules are at their usual default settings.

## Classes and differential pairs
component class Header: J22A
net class MV: NetR48_1 NetR51_1 NetR60_1 NetR61_1 NetR84_1 NetR85_1
net class HV: 12Vp_h BB_BYPAS DRV_Relay NetC39_1 NetC40_2 NetD9_1 NetD11_1 NetD12_1 NetR47_1 NetR50_1 SWNODE VBB Vbulk Vbulk1
component class PMP41026B_MAIN_PFC: C2 C39 C40 C41 C42 C44 C45 C48 C52 C53 C54 C55 C56 C57 C58 C59 C60 C61 C62 C63 C64 C65 C66 C67 C68 C69 C70 C71 C73 C74 C75 C76 C215 D1 D2 D8 D9 D10 D11 D12 D15 J5 L1 L2 L3 L4 L5 PGND Q4 Q5 Q7 R57 R58 R60 R61 R62 R64 R65 R77 R82 R83 R84 R85 R86 R87 R88 R89 R90 R91 R98 R150 R248 R249 R251 R271 RT2 U7 U8 U9 U10 U11 U12
component class PMP41026B_MAIN_PFC_Control: !PCB C26 C31 C32 C33 J21A J21M J22A J22M Logo1 R42 R43 R45 R46 R47 R48 R49 R50 R51 R52 U1 U4 U5
net class AC: "0.5mR*2 should be good?" +BRDG_N "Consider reduce if cannot fit in" Line N "Need remove then short on load side" NetC41_2 NetC44_1 NetC57_1 NetJ2_2 NetJ2_3 NetJ2_6 NetJ2_7 NetJ2_9 NetJ2_11 NetJ2_13 NetJ2_15 NetJ2_17 NetJ2_19 NetT1_3 NetT1_6 NetU6_8 NetU6_9 NetU13_6 NetU15_6 Neutral Nout "Place on proper position to desolder" "Rdson=1mR *3 should be good?" "When do PSKILL detection,"
component class PMP41026_MAIN_LLC: C1 C3 C4A C6 C7 C8 C9 C10 C11 C13 C14 C15 C16 C17 C18 C19 C20 C21 C22 C23 C24 C25 C27 C28 C29 C30 C34 C35 C36 C981 C982 D3 D4 J1 J2 J4 L6 Q1 Q2 Q3 Q6 Q8 Q9 Q10 R1 R2 R3 R4 R5 R6 R7 R8 R9 R10 R11 R12 R13 R14 R15 R16 R17 R18 R19 R20 R21 R22 R23 R24 RJ01 RJ02 U2 U3 U6 U13 U14 U15 U20 U31

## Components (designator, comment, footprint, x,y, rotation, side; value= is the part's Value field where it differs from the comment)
Brd1 "LLC XFMR" XFMR-PMP41114 122.363,49.351 r0 top
C1 "GRM188R71E104KA01D" 0603 125.6,57.6 r0 bottom value=0.1uF
C2 "B58031U5105M062" FP-B58031U5105M062_SMD2-MFG 74.5,52.2 r180 top value=1µF
C3 "B58031U5105M062" FP-B58031U5105M062_SMD2-MFG 74.5,43.3 r0 top value=1µF
C4 "EKYB630ELL331MJ25S" KYB_1000x2500 153.1,28.5 r0 top value=330uF
C4A "EKYB630ELL331MJ25S" KYB_1000x2500 130.3,39.2 r90 top value=330uF
C5 "EKYB630ELL331MJ25S" KYB_1000x2500 142.2,28.5 r0 top value=330uF
C6 "EKYB630ELL331MJ25S" KYB_1000x2500 131.4,28.5 r0 top value=330uF
C7 "GRM1885C1H221JA01D" 0603 122,38.6 r180 bottom value=220pF
C8 "GRM188R71E104KA01D" 0603 119.6,41.9 r270 bottom value=0.1uF
C9 "GRM155R71E222KA01D" 0402 106.1,7.1 r180 bottom value=2200pF
C10 "GRM188R71E104KA01D" 0603 124.7,55.1 r90 bottom value=0.1uF
C11 "GRM21BR61E226ME44L" 0805_HV 128.8,47.116 r270 bottom value=22uF
C13 "GRM1885C1H221JA01D" 0603 122.3,44.5 r180 bottom value=220pF
C14 "885012206120" FP-885012206120_0603-MFG 137.4,37.2 r0 bottom value=100nF
C15 "GRM155R61A105KE15D" 0402 101.1,34.5 r0 bottom value=1uF
C16 "GRM155R61A105KE15D" 0402 115.5,34.1 r90 bottom value=1uF
C17 "GRM188Z71C225KE43" 0603 111.85,14.675 r90 bottom value=2.2uF
C18 "GRM155R71C104KA88D" 0402 109.65,15.575 r0 bottom value=0.1uF
C19 "0402YC101KAT2A" 0402 117.2,12.7 r90 bottom value=100pF
C20 "KAF21KR72A105KU" 0805_150 142.9,41.6 r90 bottom value=1uF
C21 "GRM188R71E104KA01D" 0603 136.7,39.6 r270 bottom value=0.1uF
C22 "GRM155R61A105KE15D" 0402 101.1,33.3 r0 bottom value=1uF
C23 "GRM155R71H471KA01D" 0402 113.95,19.975 r180 bottom value=470pF
C24 "885012205027" 0402 110.75,20.275 r0 bottom value=2200pF
C25 "C0603C103J5RAC7867" FP-C0603C103J5RAC7867_0603-MFG 112.62,9.56 r270 bottom value=10nF
C26 "LMK107B7105KA-T" 0603 33.5,12.7 r90 bottom value=1uF
C27 "GRM155R71H471KA01D" 0402 111.96,11.87 r270 bottom value=470pF
C28 "GRM155R71H471KA01D" 0402 116.15,12.675 r90 bottom value=470pF
C29 "GRM155R71E104KE14D" 0402 125.7,18.5 r90 bottom value=0.1uF
C30 "GRM155R71E104KE14D" 0402 124,20.6 r180 bottom value=0.1uF
C31 "06033C104JAT2A" 0603 56.9,10.3 r0 top value=0.1uF
C32 "06033C104JAT2A" 0603 56.9,8.8 r0 top value=0.1uF
C33 "06033C104JAT2A" 0603 64.2,10 r180 top value=0.1uF
C34 "GRM21BR61E226ME44L" 0805_HV 124.284,22.4 r0 bottom value=22uF
C35 "GRM21BR61E226ME44L" 0805_HV 124.084,11.2 r0 bottom value=22uF
C36 "GRM21BR61E226ME44L" 0805_HV 124.1,13.3 r0 bottom value=22uF
C39 "06033C104JAT2A" 0603 56.2,42.6 r270 bottom value=0.1uF
C40 "06033C104JAT2A" 0603 72,46.4 r270 bottom value=0.1uF
C41 "DE6E3KJ222MN3A" E_900x700x900 11.2,2.9 r0 top value=2200pF
C42 "DE6E3KJ222MN3A" E_900x700x900 13.1,62.2 r0 top value=2200pF
C44 "F862BY474K310Z" FP-F862BY474K310Z_RADIAL-MFG 16.5,24.7 r180 top value=470nF
C45 "890334026030" FP-890334026030_RADIAL-MFG 20.6,35.5 r0 top value=1.5µF
C48 "DE6E3KJ222MN3A" E_900x700x900 3.7,16.5 r270 top value=2200pF
C52 "GRM32QR72J223KW01L" 1210_150 55.3,66.3 r270 top value=0.022uF
C53 "GRM32QR72J223KW01L" 1210_150 55.3,66.3 r270 bottom value=0.022uF
C54 "GRM155R70J105KA12D" 0402 49.9,7.7 r270 bottom value=1uF
C55 "GRM155R70J104KA01D" 0402 51.1,7.7 r270 bottom value=0.1uF
C56 "GRM155R60J102KA01D" 0402 49.9,4.8 r90 bottom value=1000pF
C57 "0805YD106MAT2A" 0805_HV 22.925,67.35 r270 bottom value=10uF
C58 "0402YC101KAT2A" 0402 41.25,32.2 r90 bottom value=100pF
C59 "0805YD106MAT2A" 0805_HV 20.55,67.3 r270 bottom value=10uF
C60 "C3216X7R1E105K085AA" 1206 39.6,34.7 r180 bottom value=1uF
C61 "C1608X7R1E105K080AB" 0603 24.85,67.675 r90 bottom value=1uF
C62 "GRM155R70J104KA01D" 0402 69.2,9.5 r270 top value=0.1uF
C63 "GRM155R70J104KA01D" 0402 74.5,9.3 r90 top value=0.1uF
C64 "06035A102KAT2A" 0603 37.525,66.75 r0 bottom value=1000pF
C65 "06035A102KAT2A" 0603 37.525,68.225 r0 bottom value=1000pF
C66 "C0603X103K5RACTU" 0603 34.7,65.425 r270 bottom value=0.01uF
C67 "C1206H104J3GACTU" 1206_190 75.3,18.9 r0 bottom value=0.1uF
C68 "0402YC101KAT2A" 0402 81.6,9.8 r180 top value=100pF
C69 "0402YC101KAT2A" 0402 81.6,11 r180 top value=100pF
C70 "C3216X7R1A106M160AC" 1206 91.2,20.8 r0 bottom value=10uF
C71 "C0805C105K3RACTU" 0805_HV 90.825,18.125 r180 bottom value=1uF
C73 "CL21A226KQQNNNE" 0805_HV 87.6,15.775 r90 bottom value=22uF
C74 "C3216X7R1E105K085AA" 1206 80.9,18.6 r180 bottom value=1uF
C75 "GRM188R71E102KA01D" 0603 78.6,10.1 r0 top value=1000pF
C76 "0402YC104KAT2A" 0402 81.6,8.6 r180 top value=0.1uF
C114 "450HXW180MEFR16X50" FP-450HXW180MEFR16X50_RADIAL-MFG 43.1,14.5 r90 top value=180µF
C120 "450HXW180MEFR16X50" FP-450HXW180MEFR16X50_RADIAL-MFG 43.1,14.5 r90 top value=180µF
C123 "450HXW180MEFR16X50" FP-450HXW180MEFR16X50_RADIAL-MFG 99.5,14.55 r90 top value=180µF
C130 "450HXW180MEFR16X50" FP-450HXW180MEFR16X50_RADIAL-MFG 99.5,14.6 r90 top value=180µF
C215 "GRM155R72A332KA01D" 0402 91.9,11.4 r270 bottom value=3300pF
C981 "GRM155R70J104KA01D" 0402 123.7,8.7 r270 bottom value=0.1uF
C982 "GRM155R70J104KA01D" 0402 119.2,7.499 r90 bottom value=0.1uF
D1 "VS-15EVL06-M3/I" "FP-VS-15AWL06FN-M3_D-PAK (TO-252AA)-MFG" 38.8,40 r180 top
D2 "VS-15EVL06-M3/I" "FP-VS-15AWL06FN-M3_D-PAK (TO-252AA)-MFG" 38.6,51.7 r180 top
D3 "B180B-13-F" SMB 133.7,39.6 r90 bottom value=80V
D4 "BAS516,115" SOD-523 114.265,9.851 r270 bottom value=100V
D8 "MBR140SFT1G" SOD-123FL 54.2,43 r270 bottom value=40V
D9 "DFLR1600-7" PowerDI123 51.4,18.4 r180 bottom value=600V
D10 "MBR140SFT1G" SOD-123FL 70.7,42.7 r90 bottom value=40V
D11 "FFA60UA60DN" FP-FFA60UA60DN_SC-65-MFG 60.5,26.075 r270 top
D12 "DFLR1600-7" PowerDI123 51.3,13.4 r180 bottom value=600V
D15 "DFLR1600-7" PowerDI123 30.1,68.025 r0 top value=600V
J1 "LPPB102CFFN-RC" Sullins_LPPB102CFFN 137.315,4.765 r180 top
J2 "LPPB102CFFN-RC" Sullins_LPPB102CFFN 105.215,4.765 r180 top
J4 "951214-8622-AR" FP-951214-8622-AR_HDR14-MFG 155.8,14.4 r270 top
J5 "4793.8000" FP-4793.8000_RCPT_IEC320-C20-MFG -0.3,16.7 r90 top
J21A "LPPB102CFFN-RC" Sullins_LPPB102CFFN 97.585,30.535 r0 bottom
J21M "LPPB102CFFN-RC" Sullins_LPPB102CFFN 59.885,4.765 r180 top
J22A "20021111-00008T4LF" FCI_20021111-00008xxLF 123.095,30.535 r90 top
J22M "LPPB102CFFN-RC" Sullins_LPPB102CFFN 76.515,4.765 r180 top
L1 "PAL6598.104NLT" FP-PAL6281.104NL_PTH_20MM5_11MM0-MFG 80,28.5 r0 top value=100uH
L2 "PAC6596NL" FP-PAC6270NL_PTH_TRANSFORMER_30MM0_19MM0-MFG 22.4,50.3 r0 top
L3 "PAC6597NL" FP-PAC6280NL_PTH_25MM0_12MM5-MFG 20,12.6 r0 top value=8.3mH
L4 "PAL6585" FP-PAL6269NL_PTH_32MM0_27MM8-MFG 53.5,45.1 r180 top value=300uH
L5 "74438336022" FP-74438336010_SMD2-MFG 88.525,11.75 r180 bottom
L6 "74438323100" VLS252010HBX 120.7,16.7 r180 bottom value=10uH
Logo1 "WEEE logo" WEEE_Minimum 144.29,13.4 r0 top
Q1 "IQD016N08NM5CGATMA1" FP-IQD016N08NM5CGATMA1_TTFN-9-MFG 146.4,33.2 r90 bottom
Q2 "IQD016N08NM5CGATMA1" FP-IQD016N08NM5CGATMA1_TTFN-9-MFG 146.4,33.1 r90 top
Q3 "IQD016N08NM5CGATMA1" FP-IQD016N08NM5CGATMA1_TTFN-9-MFG 151.7,33.1 r90 top
Q4 "IPT60R022S7XTMA1" FP-IPT60R080G7XTMA1_HSOF-8-MFG 63.8,51.4 r180 bottom
Q5 "IPT60R022S7XTMA1" FP-IPT60R080G7XTMA1_HSOF-8-MFG 63.6,36.8 r0 bottom
Q6 "IQD016N08NM5CGATMA1" FP-IQD016N08NM5CGATMA1_TTFN-9-MFG 151.7,33.2 r90 bottom
Q7 "IPP60R060P7XKSA1" TO-220AB_100mil 46.2,26.6 r180 top
Q8 "SMMBT2907ALT3G" FP-SMMBT2907ALT3G_SOT23-MFG 109.91,12 r90 bottom value=-60V
Q9 "NDS0605" SOT-23 110,8.575 r270 bottom value=-60V
Q10 "2N7002DW" SOT-363 114.15,12.675 r0 bottom value=60V
R1 "CRCW0402120KFKED" 0402 122.3,37.2 r0 bottom value=120k
R2 "CSS2H-2512R-L500F" FP-CSS2H-2512R-L500F_2512-MFG 153.1,44.3 r90 bottom value=500µ
R3 "CSS2H-2512R-L500F" FP-CSS2H-2512R-L500F_2512-MFG 153.1,44.3 r90 top value=500µ
R4 "CSS2H-2512R-L500F" FP-CSS2H-2512R-L500F_2512-MFG 156.7,44.3 r90 top value=500µ
R5 "CSS2H-2512R-L500F" FP-CSS2H-2512R-L500F_2512-MFG 156.7,44.3 r90 bottom value=500µ
R6 "MCR01MZPF1001" 0402 125.1,40.9 r180 bottom value=1.00k
R7 "CRCW04025K10JNED" 0402 106.8,8.9 r270 bottom value=5.1k
R8 "MCR01MZPF1001" 0402 125.1,42.3 r180 bottom value=1.00k
R9 "CRCW0402120KFKED" 0402 122.1,46.01 r0 bottom value=120k
R10 "MCR01MZPF1001" 0402 125.3,59 r180 bottom value=1.00k
R11 "RMCF0402FT100R" FP-RMCF0402FT100R_0402-MFG 139.6,37.2 r0 bottom value=100
R12 "ERJ-2RKF2400X" 0402 109.05,14.175 r0 bottom value=240
R13 "CRCW040215R0FKED" 0402 115.55,10.22 r270 bottom value=15.0
R14 "CRCW040230K0FKED" 0402 113.84,14.52 r0 bottom value=30.0k
R15 "RC0402FR-07100RL" 0402 115.871,20.708 r270 bottom value=100
R16 "RC0402FR-0715KL" 0402 113.85,15.675 r0 bottom value=15.0k
R17 "MCR01MZPF1001" 0402 127,38.9 r90 bottom value=1.00k
R18 "RC0402FR-07100RL" 0402 152.8,18.3 r90 bottom value=100
R19 "RC0402FR-07100RL" 0402 151.5,18.3 r270 bottom value=100
R20 "ERJ-2RKF1002X" 0402 120.8,19.3 r180 bottom value=10.0k
R21 "RC0402JR-070RL" 0402 124.7,16.4 r180 bottom value=0
R22 "RC0402FR-0745K3L" 0402S 122.8,15.8 r90 bottom value=45.3k
R23 "ERJ-2RKF1002X" 0402 124.7,15.3 r0 bottom value=10.0k
R24 "RC0402JR-070RL" 0402 129,44.4 r0 bottom value=0
R42 "CRCW0402787KFKED" 0402 35.1,15.9 r270 bottom value=787k
R43 "CRCW04027K50FKED" 0402 36.3,15.9 r270 bottom value=7.50k
R45 "CRCW0402787KFKED" 0402 37.5,15.9 r270 bottom value=787k
R46 "CRCW04027K50FKED" 0402 38.8,12.8 r270 bottom value=7.50k
R47 "RC1206FR-07348KL" 1206 57.9,19.6 r180 top value=348k
R48 "RC1206FR-07348KL" 1206 62.9,19.6 r180 top value=348k
R49 "RC1206FR-07348KL" 1206 67.7,19.6 r180 top value=348k
R50 "RC1206FR-07348KL" 1206 73.6,34.7 r90 bottom value=348k
R51 "RC1206FR-07348KL" 1206 73.6,29.8 r90 bottom value=348k
R52 "RC1206FR-07348KL" 1206 73.6,25 r90 bottom value=348k
R57 "CRCW060310K0FKEA" 0603 57.8,42.6 r90 bottom value=10.0k
R58 "CRCW06035R11FKEA" 0603 57,45 r180 bottom value=5.11
R60 "RC1206FR-07348KL" 1206 57.1,18.2 r180 bottom value=348k
R61 "RC1206FR-07348KL" 1206 62,18.2 r180 bottom value=348k
R62 "RC1206FR-07348KL" 1206 66.9,18.2 r180 bottom value=348k
R64 "ERJ-8ENF1001V" 1206 73.29,42.41 r90 bottom value=1.00k
R65 "CRCW060310K0FKEA" 0603 70.4,46.4 r90 bottom value=10.0k
R77 "CRCW060310K0FKEA" 0603 36.4,32 r270 bottom value=10.0k
R82 "RC0402JR-070RL" 0402 53,7 r0 bottom value=0
R83 "RC0402JR-070RL" 0402 53,8.4 r0 bottom value=DNP
R84 "RC1206FR-07348KL" 1206 57,13.6 r180 bottom value=348k
R85 "RC1206FR-07348KL" 1206 61.9,13.6 r180 bottom value=348k
R86 "RC0402JR-070RL" 0402 51.1,4.8 r90 bottom value=0
R87 "RC1206FR-07348KL" 1206 66.8,13.6 r180 bottom value=348k
R88 "CRCW04020000Z0ED" 0402 41.25,29.7 r90 bottom value=0
R89 "CRCW0603200RFKEA" 0603 33.5,68.15 r0 top value=200
R90 "CRCW060310R0JNEAHP" 0603 38.7,27.9 r0 bottom value=10
R91 "CRCW06030000Z0EA" 0603 36.4,28.7 r270 bottom value=0
R98 "CRCW06030000Z0EA" 0603 78.65,8.5 r180 top value=0
R150 "WSLP39212L500FEA" FP-WSLP3921L1000FEA_3921-MFG 36.1,14.2 r90 top value=2.5m
R248 "CRCW040276K8FKED" 0402 85.9,17.8 r270 bottom value=76.8k
R249 "CRCW0603118KFKEA" 0603 92.1,15.6 r90 bottom value=118k
R251 "RC0402FR-07100KL" 0402 85.9,15.2 r270 bottom value=DNP
R271 "RC0402FR-07100KL" 0402 90.8,11.4 r270 bottom value=100k
RJ01 "ERJ-2GE0R00X" FP-ERJ-2GE0R00X_0402-MFG 149.1,44.6 r0 bottom value=0
RJ02 "ERJ-2GE0R00X" FP-ERJ-2GE0R00X_0402-MFG 149.1,43.3 r0 bottom value=0
RT2 "B59751B0120A070" TDK_B751 33.6,24.7 r270 top value=50
U1 "SN74LVC2G07DCKT" DCK0006A_N 70.4,9 r270 bottom
U2 "TLV376IDBVR" DBV0005A_N 122.2,41.5 r270 bottom
U3 "LM5050MK-1/NOPB" DDC0006A_N 139.725,39.5 r0 bottom
U4 "LMP7717MF/NOPB" DBV0005A_N 36.4,12.425 r270 bottom
U5 "REF2025AIDDCR" DDC0005A_L 60.6,9.4 r180 top
U6 "XTR111AIDGQT" DGQ0010D_N 112.325,17.775 r0 bottom
U7 "TMCS1100A1DT" D0008A_N 48.9,5.8 r0 top
U8 "UCC27511DBVR" DBV0006A_N 38.9,30.8 r90 bottom
U9 "UCC27712DR" D0008A_N 30.125,66.465 r180 bottom
U10 "TLV71333PDBVR" DBV0005A_N 72,9.4 r180 top
U11 "UCC21220DR" D0016B 77.9,13.3 r90 bottom
U12 "TPS62901RPJR" RPJ0009A 89.775,15.4 r90 bottom
U13 "ISO7762FDWR" DW0016B-MFG 108.9,39.4 r180 bottom
U14 "SN74LVC1G3208DCKR" DCK0006A_N 100.6,36.2 r180 bottom
U15 "TPS562211DRLR" DRL0008A 123.5,18.6 r270 bottom
U20 "TLV71333PDBVR" DBV0005A_N 121.3,8.199 r270 bottom
U31 "TMCS1133B8QDVGR" DVG0010A-MFG 117.6,57.7 r0 bottom

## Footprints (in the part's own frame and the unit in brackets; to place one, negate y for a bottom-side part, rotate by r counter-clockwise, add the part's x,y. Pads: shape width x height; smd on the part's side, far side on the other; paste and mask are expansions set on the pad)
0402 [mm] "0402 from SM-752 data"
  rect 0.8x0.6 smd: 1(-0.6,0) 2(0.6,0)
  silkscreen extent -1.22,-0.52 1.22,0.52, body extent -0.55,-0.3 0.55,0.3, height 0.6
0402S [mil] "Based on C0402S footprint from PADS legacy"
  rect 15x24 smd: 1(-20,0) 2(20,0)
  body extent -22,-12 22,12, height 24
0603 [mm] "0603 from SM-752 data"
  rect 1x0.95 smd: 1(-0.8,0) 2(0.8,0)
  silkscreen extent -1.52,-0.69 1.52,0.69, body extent -0.87,-0.47 0.87,0.47, height 1
0805_150 [mm] "0805 / 1.5 mm height"
  rect 1.15x1.45 smd: 1(-0.9,0) 2(0.9,0)
  silkscreen extent -0.1,-0.8 0.1,0.8, body extent -1.1,-0.72 1.1,0.72, height 1.5
0805_HV [mil] "0805 with 30mil clearance between pads"
  rect 50x63 smd: 1(-40,0) 2(40,0)
  silkscreen extent -74,-40 74,40, body extent -43,-29 43,29, height 57
1206 [mm] "1206 from SM-752 data"
  rect 1.3x1.85 smd: 1(-1.45,0) 2(1.45,0)
  silkscreen extent -2.4,-1.21 2.4,1.21, body extent -1.7,-0.9 1.7,0.9, height 1.35
1206_190 [mm] "1206_190"
  rect 1.1x1.6 smd: 1(-1.7,0) 2(1.7,0)
  silkscreen extent -0.9,-1 0.9,1, body extent -1.75,-0.95 1.75,0.95, height 1.9
1210_150 [mm] "1210"
  rect 1.3x2.7 smd: 1(-1.45,0) 2(1.45,0)
  silkscreen extent -2.32,-1.57 2.32,1.57, body extent -1.7,-1.35 1.7,1.35, height 1.5
D0008A_N [mm] "SOIC, 8-Leads, Body 4.9x3.9mm, Pitch 1.27mm, IPC Medium Density"
  oval 1.45x0.6 smd: 1(-2.725,1.905) 2(-2.725,0.635) 3(-2.725,-0.635) 4(-2.725,-1.905) 5(2.725,-1.905) 6(2.725,-0.635) 7(2.725,0.635) 8(2.725,1.905)
  silkscreen extent -3.3,-2.5 0.9,2.5, body extent -3,-2.45 3,2.45, height 1.63
D0016B [mm] "SOIC-16"
  rrect17% 1.4x0.6 smd: 1(-2.75,4.445) 2(-2.75,3.175) 3(-2.75,1.905) 4(-2.75,0.635) 5(-2.75,-0.635) 6(-2.75,-1.905) 7(-2.75,-3.175) 8(-2.75,-4.445) 9(2.75,-4.445) 10(2.75,-3.175) 11(2.75,-1.905) 12(2.75,-0.635) 13(2.75,0.635) 14(2.75,1.905) 15(2.75,3.175) 16(2.75,4.445)
  body extent -3.01,-4.95 3.01,4.95, height 1.75
DBV0005A_N [mm] "SOT23, 5-Leads, Body 2.9x1.6mm, Pitch 0.95mm, Lead Span 2.8mm, IPC Medium Density"
  rrect17% 1x0.6 smd: 1(-1.375,0.95) 2(-1.375,0) 3(-1.375,-0.95) 4(1.375,-0.95) 5(1.375,0.95)
  silkscreen extent -0.25,-1.55 0.25,1.55, body extent -1.42,-1.46 1.42,1.46, height 1.09
DBV0006A_N [mm] "SOT23, 6-Leads, Body 2.9x1.6mm, Pitch 0.95mm, Lead Span 2.8mm, IPC Medium Density"
  rrect17% 1x0.6 smd: 1(-1.375,0.95) 2(-1.375,0) 3(-1.375,-0.95) 4(1.375,-0.95) 5(1.375,0) 6(1.375,0.95)
  silkscreen extent -1.68,-1.55 0.5,1.55, body extent -1.42,-1.46 1.42,1.46, height 1.12
DCK0006A_N [mm] "SOT23, 6-Leads, Body 2x1.3mm, Pitch 0.65mm, Lead Span 2.1mm, IPC Medium Density"
  rrect25% 0.85x0.4 smd: 1(-1.125,0.65) 2(-1.125,0) 3(-1.125,-0.65) 4(1.125,-0.65) 5(1.125,0) 6(1.125,0.65)
  silkscreen extent -1.5,-1.09 0.51,1.09, body extent -1.14,-1 1.14,1, height 0.95
DDC0005A_L [mm]
  rrect18% 0.8x0.55 smd: 1(-1.275,0.95) 2(-1.275,0) 3(-1.275,-0.95) 4(1.275,-0.95) 5(1.275,0.95)
  silkscreen extent -1.25,-1.52 0.88,1.57, body extent -1.41,-1.45 1.41,1.45, height 1.1
DDC0006A_N [mm]
  rrect17% 1x0.6 smd: 1(-1.375,0.95) 2(-1.375,0) 3(-1.375,-0.95) 4(1.375,-0.95) 5(1.375,0) 6(1.375,0.95)
  silkscreen extent -1.75,-1.52 0.7,1.53, body extent -1.43,-1.48 1.43,1.49, height 0.92
DGQ0010D_N [mm] "TSSOP, 10-Leads, Body 3x3mm, Pitch 0.5mm, Thermal Pad 1.88x1.57mm, IPC Medium Density"
  rrect100% 1.35x0.3 smd: 1(-2.225,1) 2(-2.225,0.5) 3(-2.225,0) 4(-2.225,-0.5) 5(-2.225,-1) 6(2.225,-1) 7(2.225,-0.5) 8(2.225,0) 9(2.225,0.5) 10(2.225,1)
  rrect9% 2.2x3.1 smd paste-2 mask-2: 11(0,0)
  rrect5% 1.83x1.89 on Bottom Paste: 11(0,0)
  rrect5% 1.83x1.89 on Bottom Solder: 11(0,0)
  silkscreen extent -2.65,-1.55 0.9,1.55, body extent -2.46,-1.5 2.46,1.5, height 1.1
DRL0008A [mm] "SOT-5X3-8"
  rrect33% 0.67x0.3 smd: 1(-0.74,0.75) 2(-0.74,0.25) 3(-0.74,-0.25) 4(-0.74,-0.75) 5(0.74,-0.75) 6(0.74,-0.25) 7(0.74,0.25) 8(0.74,0.75)
  body extent -0.8,-1.05 0.8,1.05, height 0.61
DVG0010A-MFG [mm]
  rrect6% 1.65x4.41 smd paste+0 mask+0: 1(-4.875,2.54) 2(-4.875,-2.54)
  rrect17% 1.65x0.6 smd paste+0 mask+0: 3(4.875,-4.445) 4(4.875,-3.175) 5(4.875,-1.905) 6(4.875,-0.635) 7(4.875,0.635) 8(4.875,1.905) 9(4.875,3.175) 10(4.875,4.445)
  silkscreen extent -6.37,-5.25 3.67,5.25, body extent -5.15,-5.15 5.15,5.15, height 2.65
DW0016B-MFG [mm]
  rrect17% 1.65x0.6 smd paste+0 mask+0: 1(-4.875,4.445) 2(-4.875,3.175) 3(-4.875,1.905) 4(-4.875,0.635) 5(-4.875,-0.635) 6(-4.875,-1.905) 7(-4.875,-3.175) 8(-4.875,-4.445) 9(4.875,-4.445) 10(4.875,-3.175) 11(4.875,-1.905) 12(4.875,-0.635) 13(4.875,0.635) 14(4.875,1.905) 15(4.875,3.175) 16(4.875,4.445)
  silkscreen extent -6.38,-5.25 3.5,5.25, body extent -5.15,-5.15 5.15,5.15, height 2.65
E_900x700x900 [mm] "TH, 2- Leads, Body 9x7mm, Pin Spacing 7.5mm"
  round 1.4 hole 0.9: 1(-3.75,0) 2(3.75,0)
  silkscreen extent -4.5,-3.5 4.5,3.5, body extent -4.49,-3.5 4.49,3.5, height 11.96
FCI_20021111-00008xxLF [mm] "Header, 1.27mm, 4x2, TH"
  rect 0.95x0.95 hole 0.65 mask+0.08: 1(-0.635,1.905)
  round 0.95 hole 0.65 mask+0.08: 2(0.635,1.905) 3(-0.635,0.635) 4(0.635,0.635) 5(-0.635,-0.635) 6(0.635,-0.635) 7(-0.635,-1.905) 8(0.635,-1.905)
  silkscreen extent -2,-2.54 1.7,2.54, body extent -1.7,-2.54 1.7,2.54, height 5.5
FP-450HXW180MEFR16X50_RADIAL-MFG [mm]
  rrect7% 1.45x1.45 hole 0.95 paste-2539.97 mask+0: 1(-3.75,0)
  round 1.45 hole 0.95 paste-2539.97 mask+0: 2(3.75,0)
  silkscreen extent -8.25,-8.25 8.25,8.25, body extent -8,-52 7.99,4, height 16.36
FP-4793.8000_RCPT_IEC320-C20-MFG [mm]
  body extent -14,-4.05 14,27.45, height 33
FP-951214-8622-AR_HDR14-MFG [mm]
  rrect8% 1.3x1.3 hole 0.8 paste-2539.97 mask+0: 1(-6,-1)
  round 1.3 hole 0.8 paste-2539.97 mask+0: 2(-6,1) 3(-4,-1) 4(-4,1) 5(-2,-1) 6(-2,1) 7(0,-1) 8(0,1) 9(2,-1) 10(2,1) 11(4,-1) 12(4,1) 13(6,-1) 14(6,1)
  silkscreen extent -7.82,-2.1 7.1,2.1, body extent -7.2,-2.2 7.2,2.2, height 0.25
FP-74438336010_SMD2-MFG [mm]
  rrect8% 1.3x3.4 smd paste+0 mask+0: 1(-1.05,0) 2(1.05,0)
  silkscreen extent -1.6,-2.1 1.6,2.1, body extent -1.5,-1.5 1.5,1.5, height 2
FP-885012206120_0603-MFG [mm]
  rrect13% 0.8x0.8 smd paste+0 mask+0: 1(-0.75,0) 2(0.75,0)
  silkscreen extent -0.85,-0.77 0.85,0.77, body extent -0.8,-0.4 0.8,0.4, height 0.87
FP-890334026030_RADIAL-MFG [mm]
  rrect6% 1.7x1.7 hole 1.1 paste-2539.97 mask+0: 1(-11.25,0)
  round 1.7 hole 1.1 paste-2539.97 mask+0: 2(11.25,0)
  silkscreen extent -13.25,-5.25 13.25,5.25, body extent -13.35,-5.35 13.35,5.35, height 0.25
FP-B58031U5105M062_SMD2-MFG [mm]
  rrect4% 2.45x8.85 smd paste+0 mask+0: 1(-3.475,0) 2(3.475,0)
  silkscreen extent -1.88,-4.18 1.88,4.18, body extent -3.57,-3.93 3.57,3.93, height 4.5
FP-C0603C103J5RAC7867_0603-MFG [mm]
  rrect13% 0.75x0.9 smd paste+0 mask+0: 1(-0.6,0) 2(0.6,0)
  silkscreen extent -0.87,-0.82 0.87,0.82, body extent -0.8,-0.4 0.8,0.4, height 0.9
FP-CSS2H-2512R-L500F_2512-MFG [mm]
  rrect6% 1.8x3.4 smd paste+0 mask+0: 1(-2.6,0) 2(2.6,0)
  silkscreen extent -1.33,-1.63 1.33,1.63, body extent -3.17,-1.53 3.17,1.53, height 1.23
FP-ERJ-2GE0R00X_0402-MFG [mm]
  rrect21% 0.475x0.5 smd paste+0 mask+0: 1(-0.512,0) 2(0.513,0)
  silkscreen extent -0.53,-0.63 0.53,0.63, body extent -0.5,-0.25 0.5,0.25, height 0.4
FP-F862BY474K310Z_RADIAL-MFG [mm]
  rrect6% 1.55x1.55 hole 1 paste-2539.97 mask+0: 1(-7.5,0)
  round 1.55 hole 1 paste-2539.97 mask+0: 2(7.5,0)
  silkscreen extent -9,-5.5 9,5.5, body extent -9.1,-5.6 9.1,5.6, height 0.25
FP-FFA60UA60DN_SC-65-MFG [mm]
  rrect4% 2.45x2.45 / inner round 2.45 / far side rrect4% 2.45x2.45 hole 1.6 paste-2539.97 mask+0: 1(-0.325,5.45)
  round 2.45 hole 1.6 paste-2539.97 mask+0: 2(-0.325,0) 3(-0.325,-5.45)
  silkscreen extent -2.5,-8.1 2.5,8.83, body extent -2.6,-8.2 2.6,8.2, height 0.25
FP-IPT60R080G7XTMA1_HSOF-8-MFG [mm]
  rrect13% 0.8x2.5 smd paste-1000 mask+0: 1(-4.2,-5.35) 2(-3,-5.35)
  round 0.709 smd paste-1000 mask+0: 3-4-5-6-7-8(4.206,-4.881)
  round 7.2 smd paste-1000 mask+0: 9(0,2.7)
  Top Layer region: -4.85,-1.3 4.85,-1.3 4.85,2.4 4.35,2.4 4.35,5.2 5.05,5.2 5.05,6.7 -5.05,6.7 -5.05,5.2 -4.35,5.2 -4.35,2.4 -4.85,2.4
  Top Layer region: -2.2,-4.1 4.6,-4.1 4.6,-6.6 3.8,-6.6 3.8,-4.6 3.4,-4.6 3.4,-6.6 2.6,-6.6 2.6,-4.6 2.2,-4.6 2.2,-6.6 1.4,-6.6 1.4,-4.6 1,-4.6 1,-6.6 0.2,-6.6 0.2,-4.6 -0.2,-4.6 -0.2,-6.6 -1,-6.6 -1,-4.6 -1.4,-4.6 -1.4,-6.6 -2.2,-6.6 -2.2,-4.1
  body extent -4.95,-5.79 4.95,5.89, height 2.31
FP-IQD016N08NM5CGATMA1_TTFN-9-MFG [mm]
  round 3.455 smd paste-1000 mask-1000: 1-2-3-4(-1.302,-0.207)
  round 0.81 smd paste-1000 mask-1000: 5-6-7-8(2.8,0)
  rrect20% 0.5x1.2 smd paste-1000 mask+0: 9(0.75,2.2)
  Top Layer region: 1.05,-2.155 -3.25,-2.155 -3.25,2.155 0.1,2.155 0.1,1.105 1.05,1.105
  Top Layer region: 3.25,-2.155 2.35,-2.155 2.35,2.155 3.25,2.155
  silkscreen extent -3.92,-2.55 3.05,2.55, body extent -3,-2.5 3,2.5, height 1.1
FP-PAC6270NL_PTH_TRANSFORMER_30MM0_19MM0-MFG [mm]
  rrect3% 3.2x3.2 hole 2.1 paste-2539.97 mask+0: 1(-5,-6.3)
  round 3.2 hole 2.1 paste-2539.97 mask+0: 2(5,-6.3) 3(5,6.3) 4(-5,6.3)
  silkscreen extent -15,-10.12 15,9.5, body extent -15.1,-9.6 15.1,9.6, height 0.25
FP-PAC6280NL_PTH_25MM0_12MM5-MFG [mm]
  rrect4% 2.3x2.3 hole 1.5 paste-2539.97 mask+0: 1(5.5,-4.5)
  round 2.3 hole 1.5 paste-2539.97 mask+0: 2(-5.5,-4.5) 3(-5.5,4.5) 4(5.5,4.5)
  silkscreen extent -12.5,-6.25 13.39,6.25, body extent -12.6,-6.35 12.6,6.35, height 0.25
FP-PAL6269NL_PTH_32MM0_27MM8-MFG [mm]
  round 2.3 hole 1.5 paste-2539.97 mask+0: 1(0,12) 2(0,-12)
  silkscreen extent -16,-13.9 16,14.67, body extent -16.1,-14 16.1,14, height 0.25
FP-PAL6281.104NL_PTH_20MM5_11MM0-MFG [mm]
  rrect6% 1.7x1.7 hole 1.1 paste-2539.97 mask+0: 1(0,4)
  round 1.7 hole 1.1 paste-2539.97 mask+0: 2(0,-4)
  silkscreen extent -10.25,-5.5 10.25,6.12, body extent -10.35,-5.6 10.35,5.6, height 0.25
FP-RMCF0402FT100R_0402-MFG [mm]
  rrect20% 0.5x0.6 smd paste+0 mask+0: 1(-0.5,0) 2(0.5,0)
  silkscreen extent -0.55,-0.7 0.55,0.7, body extent -0.5,-0.25 0.5,0.25, height 0.4
FP-SMMBT2907ALT3G_SOT23-MFG [mm]
  rrect13% 0.9x0.8 smd paste+0 mask+0: 1(-1,0.95) 2(-1,-0.95) 3(1,0)
  silkscreen extent -0.18,-1.52 0.7,1.52, body extent -1.2,-1.45 1.2,1.45, height 1.11
"FP-VS-15AWL06FN-M3_D-PAK (TO-252AA)-MFG" [mm]
  rrect7% 1.524x2.28 smd paste+0 mask+0: 1(-2.28,-4.56) 3(2.28,-4.56)
  rrect2% 6.74x6.23 smd paste+0 mask+0: 4(0,2.585)
  body extent -3.27,-4.98 3.27,4.93, height 2.53
FP-WSLP3921L1000FEA_3921-MFG [mm]
  rrect4% 2.7x6.2 smd paste+0 mask+0: 1(-4.15,0) 2(4.15,0)
  silkscreen extent -2.42,-2.79 2.42,2.79, body extent -5,-2.6 5,2.6, height 0.88
KYB_1000x2500 [mm] "TH, 2-Leads, Dia 10mm, Lead Spacing 5mm"
  rect 1.35x1.35 hole 0.85: 1(-2.5,0)
  round 1.35 hole 0.85: 2(2.5,0)
  silkscreen extent -6.75,-5.25 5.25,5.25, body extent -5.21,-5.24 5.24,5.24, height 26.51
PowerDI123 [mm] "Diodes Inc recommended land pattern, document number DS30628 Rev. 6-2"
  rect 2.2x1.4 smd: 1(-1.275,0)
  rect 0.9x1.4 smd: 2(1.275,0)
  silkscreen extent -3.1,-1.09 1.76,1.09, body extent -2.37,-0.96 1.53,0.97, height 1
RPJ0009A [mm] "VQFN-HR-9"
  rrect50% 0.65x0.2 smd: 1(-0.625,0.25) 2(-0.625,-0.25) 5(0.625,-0.25)
  rrect50% 1x0.2 smd: 6(0.45,0.25)
  rrect40% 0.25x0.55 smd: 7(0.5,0.925) 8(0,0.925)
  body extent -0.8,-1.05 0.8,1.05, height 1
SMB [mm] "Molded Diode, 2-Leads, Body 5.4x3.6mm, IPC Medium Density, based on OnSemi component dimensions"
  rect 2.159x2.743 smd: 1(-2.21,0) 2(2.21,0)
  silkscreen extent -3.94,-2.08 3.18,2.08, body extent -2.7,-1.8 2.7,1.8, height 2.32
SOD-123FL [mm] "Copied from SOD-123"
  rect 0.915x1.22 smd: 1(-1.637,0) 2(1.637,0)
  silkscreen extent -2.74,-1.16 1.68,1.16, body extent -1.9,-0.9 1.9,0.9, height 1
SOD-523 [mm] "NXP Semiconductor recommended land pattern, nominal STEP model"
  rect 0.8x0.6 smd paste-0.05: 1(-0.55,0) 2(0.55,0)
  silkscreen extent -1.65,-0.66 1.2,0.66, body extent -0.8,-0.4 0.8,0.4, height 0.72
SOT-23 [mm] "SOT23, 3-Leads, Body 2.9x1.3mm, Pitch 0.95mm, Lead Span 2.5mm, IPC Medium Density"
  rrect50% 1x0.6 smd: 1(-1.2,0.95) 2(-1.2,-0.95) 3(1.2,0)
  silkscreen extent -1.63,-1.5 0.7,1.5, body extent -1.16,-1.45 1.21,1.45, height 1
SOT-363 [mm]
  rect 0.6x0.42 smd mask+0.051: 1(-0.95,0.65) 2(-0.95,0) 3(-0.95,-0.65) 4(0.95,-0.65) 5(0.95,0) 6(0.95,0.65)
  silkscreen extent -0.38,-1.02 0.38,1.02, body extent -1.1,-1.1 1.1,1.1, height 1.12
Sullins_LPPB102CFFN [mm] "Receptacle, 1.27 mm, TH"
  rrect50% 0.9x0.9 hole 0.6: 1(-5.715,0.635)
  round 0.9 hole 0.6 mask+0.102: 2(-5.715,-0.635) 4(-4.445,-0.635) 6(-3.175,-0.635) 8(-1.905,-0.635) 10(-0.635,-0.635) 12(0.635,-0.635) 14(1.905,-0.635) 16(3.175,-0.635) 18(4.445,-0.635) 20(5.715,-0.635)
  round 0.9 hole 0.6: 3(-4.445,0.635) 5(-3.175,0.635) 7(-1.905,0.635) 9(-0.635,0.635) 11(0.635,0.635) 13(1.905,0.635) 15(3.175,0.635) 17(4.445,0.635) 19(5.715,0.635)
  body extent -6.55,-1.56 6.55,1.54, height 4.5
TDK_B751 [mm] "TH, 2-Leads, Dia 12.5mm, Pin Spacing 5mm"
  round 1.35 hole 0.85: 1(0,2.5) 2(0,-2.5)
  silkscreen extent -3.5,-6.25 3.5,6.25, body extent -3.48,-6.2 3.48,6.25, height 16.49
TO-220AB_100mil [mm] "High Voltage staggered pins"
  rrect50% 1.8x1.8 / inner round 1.8 / far side rrect50% 1.8x1.8 hole 1.3: 1(-2.54,0)
  round 1.8 hole 1.3: 2(0,-2.54) 3(2.54,0)
  silkscreen extent -5.77,-1.62 5.44,3.07, body extent -5.77,-2.84 5.53,3.07, height 21.61
VLS252010HBX [mm] "TDK"
  rect 0.6x2 smd: 1(-0.95,0) 2(0.95,0)
  silkscreen extent -0.25,-1.1 0.25,1.1, body extent -1.35,-1.1 1.35,1.1, height 1
WEEE_Minimum [mm] "WEEElie bin"
  silkscreen extent -2.42,-4.38 2.52,2.65
XFMR-PMP41114 [mm]
  rrect50% 0.8x2 smd far side: P1a(-39.074,-1.25) P1b(-39.074,10.71) P2a(-39.125,4.25) P2b(-39.125,16.25) P3a(-37.574,-1.25) P3b(-37.574,10.71) P4a(-37.625,4.25) P4b(-37.625,16.25) P5a(-36.074,-1.25) P5b(-36.074,10.71) P6a(-36.125,4.25) P6b(-36.125,16.25)
  rect 3.5x4 / inner rect 5x7 / far side rect 5x7 hole 3 square: P7a(-29.823,1.499) P7b(-29.822,13.499) P8a(-21.805,1.499) P8b(-21.805,13.499)
  rect 3.5x4 / inner rect 5x8 / far side rect 5x8 hole 3 square copper offset 0,1: P9a(-14.076,1.499)
  rect 3.5x4 / inner rect 5x8 / far side rect 5x8 hole 3 square: P9b(-14.075,13.499)
  rect 0.8x1.2 smd far side: S1(28.725,-0.712) S1(28.725,5.299) S1(28.725,11.299) S2(28.725,3.588) S2(28.725,9.599) S2(28.725,15.599) S3(27.225,-0.712) S3(27.225,5.299) S3(27.225,11.299) S4(27.225,3.588) S4(27.225,9.599) S4(27.225,15.599) S5(25.725,-0.712) S5(25.725,5.299) S5(25.725,11.299) S6(25.725,3.588) S6(25.725,9.599) S6(25.725,15.599)
  rect 2.5x4 / inner rect 2.5x4 / far side rect 2.5x5.5 hole 3 square: S7(23.454,1.538) S7(23.454,7.549) S7(23.454,13.549)
  rect 3.5x4 / inner rect 3.5x4 / far side rect 3.5x5.5 hole 3 square copper offset -0.25,0: S8(20.214,1.538) S8(20.214,7.549) S8(20.214,13.549)
  Keep-Out Layer board cut-out: 18.761,11.999 18.761,14.999 29.911,14.999 29.911,11.999
  Keep-Out Layer board cut-out: 18.761,5.999 18.761,8.999 29.911,8.999 29.911,5.999
  Keep-Out Layer board cut-out: -40.489,11.799 -40.489,15.199 -34.839,15.199 -34.839,11.799
  Keep-Out Layer board cut-out: 18.761,-0.011 18.761,2.989 29.911,2.989 29.911,-0.011
  Keep-Out Layer board cut-out: -40.489,-0.201 -40.489,3.199 -34.839,3.199 -34.839,-0.201
  silkscreen extent -40.51,-4.78 29.71,20, body extent -40.63,-4.18 29.7,19.33, height 32.13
